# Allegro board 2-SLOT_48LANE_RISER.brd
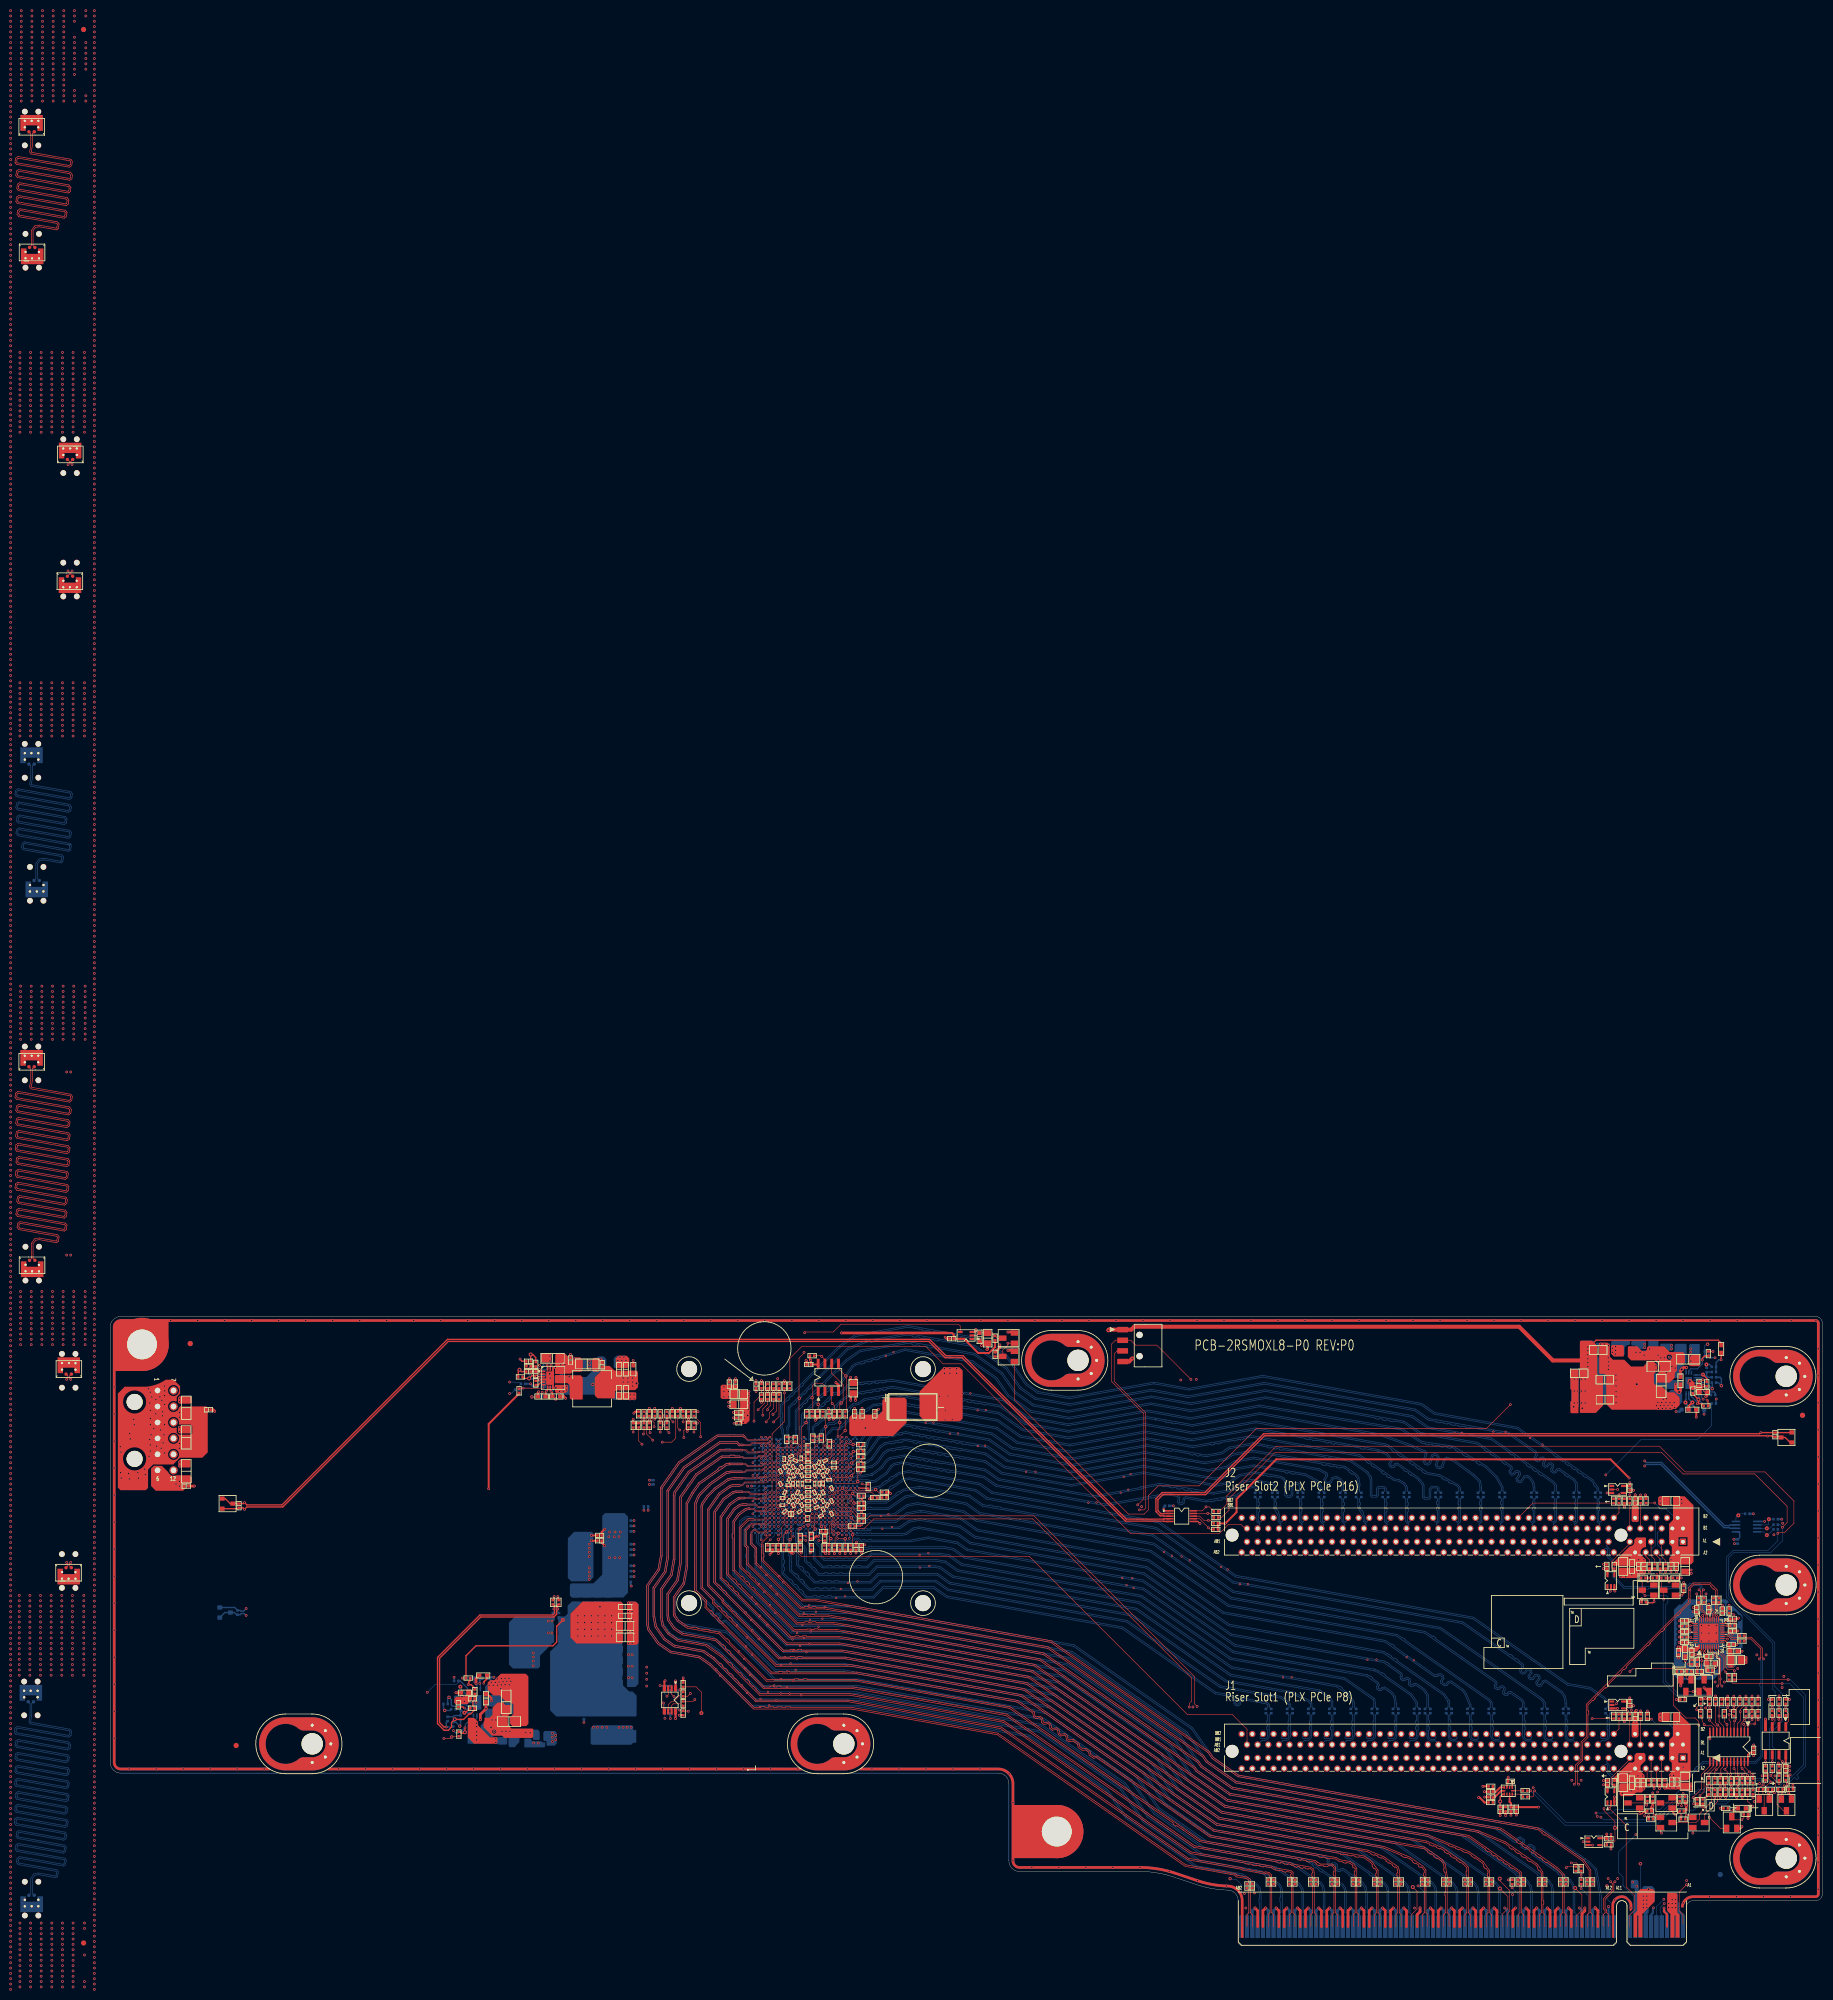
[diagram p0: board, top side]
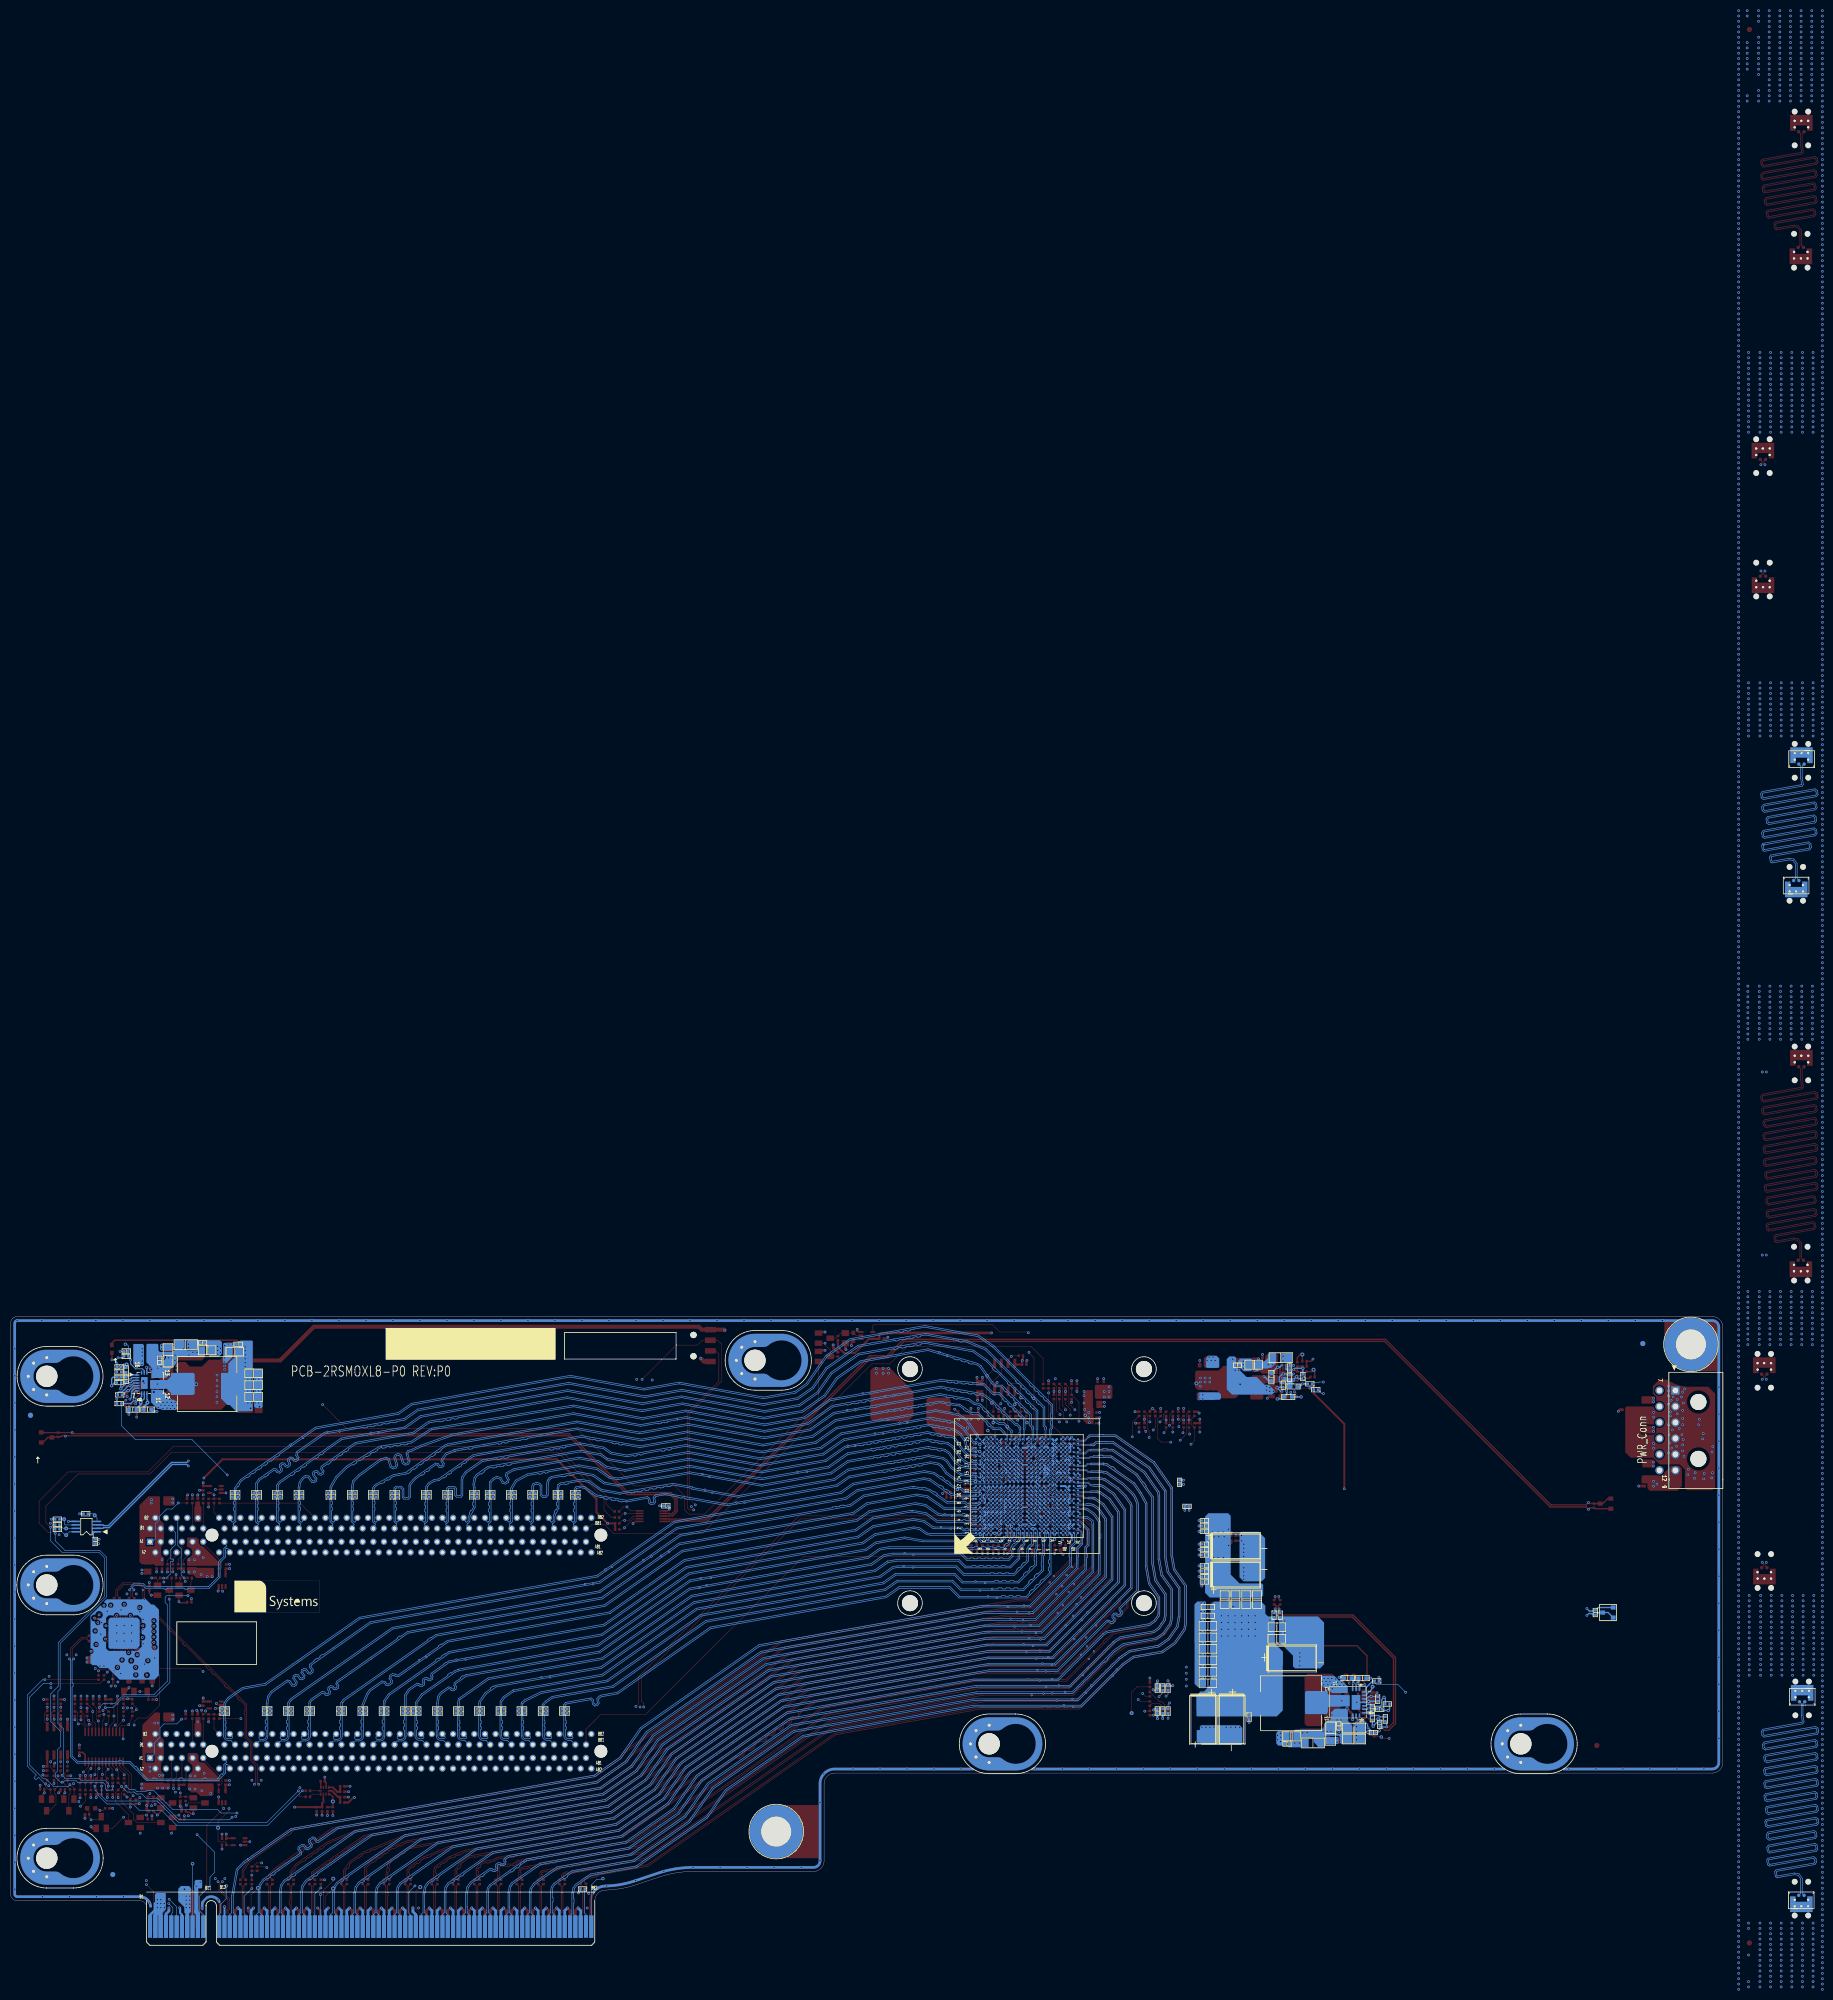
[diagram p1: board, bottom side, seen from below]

Outline 322.05 x 118.24 mm; copper layers: TOP, GND, IN1, VCC, VCC1, IN2, GND1, BOTTOM. Coordinates in mm from the lower left corner of the outline.
Outline path: 0,116.24 0,34.41 0.02,34.15 arc(0.07,33.89) 0.15,33.64 0.27,33.41 0.41,33.19 arc(0.59,32.99) 0.78,32.82 1,32.68 1.23,32.56 1.48,32.48 1.74,32.42 2,32.41 167.05,32.41 167.31,32.39 167.56,32.34 167.81,32.26 168.05,32.14 168.26,31.99 168.46,31.82 168.63,31.63 168.78,31.41 168.89,31.17 168.98,30.93 169.03,30.67 169.05,30.41 169.05,15.91 169.06,15.65 169.11,15.39 169.2,15.14 169.31,14.91 arc(169.46,14.69) 169.63,14.49 169.83,14.32 arc(170.05,14.18) 170.28,14.06 170.53,13.98 170.79,13.92 171.05,13.91 193.68,13.91 194.53,13.89 194.81,13.88 195.38,13.83 195.71,13.8 196.23,13.74 196.58,13.7 197.07,13.62 197.43,13.55 197.91,13.45 198.26,13.37 198.75,13.25 199.09,13.16 199.59,13.01 200,12.88 204.36,11.43 205.18,11.18 206,10.96 206.83,10.78 207.67,10.63 208.51,10.52 209.36,10.45 210.21,10.41 210.49,10.38 arc(210.9,10.27) 211.27,10.07 211.49,9.9 211.69,9.7 211.86,9.47 211.99,9.23 212.09,8.96 212.15,8.69 212.17,8.41 212.17,0.51 212.67,0 282.87,0 283.37,0.51 283.37,7.45 arc(284.33,8.41) 285.28,7.45 285.28,0.51 285.79,0 295.96,0 296.47,0.51 296.47,7.14 arc(296.84,8.04) 297.74,8.41 320.78,8.41 arc(321,8.43) 321.21,8.48 321.41,8.58 321.59,8.7 321.75,8.86 321.88,9.04 arc(321.97,9.24) 322.03,9.46 322.05,9.68 322.05,116.97 322.03,117.2 321.97,117.41 321.88,117.61 321.75,117.79 321.59,117.95 321.41,118.07 321.21,118.17 321,118.23 320.78,118.24 2,118.24 1.74,118.23 1.48,118.18 arc(1.12,118.04) 0.78,117.83 0.59,117.66 0.41,117.46 0.27,117.24 0.15,117.01 0.07,116.76 0.02,116.51 0,116.24

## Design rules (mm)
constraint set DEFAULT: min track width 0.102, pair gap 0.102

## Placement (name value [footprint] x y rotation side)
C1  -  [C0402]  131.4 109.22 180 top
C2  -  [C0201]  126.09 89.16 112.5 top
C3  -  [C0402]  135.21 99.95 90 top
C4  -  [C0201]  126.09 86.76 112.5 top
C5  -  [C0201]  128.09 91.96 22.5 top
C6  -  [C0201]  126.89 85.16 247.5 top
C7  -  [C0201]  127.69 89.16 67.5 top
C8  -  [C0402]  141.43 99.95 90 top
C9  -  [C0201]  128.49 89.96 292.5 top
C10  -  [C0201]  134.09 83.56 112.5 top
C11  -  [C0402]  97.51 73.41 0 bottom
C12  -  [C0402]  143.84 99.95 90 top
C13  -  [C0402]  97.51 74.42 0 bottom
C14  -  [C0201]  134.09 85.16 112.5 top
C15  -  [C0201]  127.69 83.56 67.5 top
C16  -  [C0201]  131.28 89.97 180 top
C17  -  [C0201]  126.89 89.96 112.5 top
C18  -  [C0201]  133.29 84.36 247.5 top
C19  -  [C0201]  134.89 82.76 247.5 top
C20  -  [C0201]  133.29 89.16 67.5 top
C21  -  [C0201]  135.69 83.56 292.5 top
C22  -  [C0201]  130.09 89.96 292.5 top
C23  -  [C0402]  278.83 11.94 270 top
C24  -  [C0402]  273.83 11.94 270 top
C25  -  [C0402]  269.83 11.94 270 top
C26  -  [C0402]  265.83 11.94 270 top
C27  -  [C0402]  281.26 44.07 270 bottom
C28  -  [C0402]  273.3 44.07 270 bottom
C29  -  [C0402]  269.3 44.07 270 bottom
C30  -  [C0402]  265.3 44.07 270 bottom
C31  -  [C0402]  282.28 44.07 270 bottom
C32  -  [C0402]  274.31 44.07 270 bottom
C33  -  [C0402]  270.31 44.07 270 bottom
C34  -  [C0402]  266.31 44.07 270 bottom
C35  -  [C0402]  277.82 11.94 270 top
C36  -  [C0402]  272.82 11.94 270 top
C37  -  [C0402]  268.82 11.94 270 top
C38  -  [C0402]  264.82 11.94 270 top
C39  -  [C0402]  280.34 84.71 270 bottom
C40  -  [C0402]  276.3 84.71 270 bottom
C41  -  [C0402]  272.37 84.71 270 bottom
C42  -  [C0402]  268.33 84.71 270 bottom
C43  -  [C0402]  279.33 84.71 270 bottom
C44  -  [C0402]  275.29 84.71 270 bottom
C45  -  [C0402]  271.35 84.71 270 bottom
C46  -  [C0402]  267.31 84.71 270 bottom
C47  -  [C0805]  118.24 101.73 180 top
C48  -  [C0805]  139.78 104.78 90 top
C49  -  [C0402]  118.24 100.2 180 top
C50  -  [C0402]  116.46 105.54 90 top
C51  -  [C0402]  118.24 99.19 180 top
C52  -  [C0402]  117.6 105.54 90 top
C53  -  [C0201#2]  131.17 80.24 270 top
C54  -  [C0201#2]  118.24 98.17 180 top
C55  -  [C0402]  259.3 44.07 270 bottom
C56  -  [C0402]  255.3 44.07 270 bottom
C57  -  [C0402]  251.3 44.07 270 bottom
C58  -  [C0402]  247.3 44.07 270 bottom
C59  -  [C0402]  245.26 44.07 270 bottom
C60  -  [C0402]  241.28 44.07 270 bottom
C61  -  [C0402]  237.31 44.07 270 bottom
C62  -  [C0402]  233.35 44.07 270 bottom
C63  -  [C0402]  229.31 44.07 270 bottom
C64  -  [C0402]  225.38 44.07 270 bottom
C65  -  [C0402]  221.38 44.07 270 bottom
C66  -  [C0402]  217.38 44.07 270 bottom
C67  -  [C0402]  260.31 44.07 270 bottom
C68  -  [C0402]  256.31 44.07 270 bottom
C69  -  [C0402]  252.31 44.07 270 bottom
C70  -  [C0402]  248.31 44.07 270 bottom
C71  -  [C0402]  246.28 44.07 270 bottom
C72  -  [C0402]  242.29 44.07 270 bottom
C73  -  [C0402]  238.33 44.07 270 bottom
C74  -  [C0402]  234.37 44.07 270 bottom
C75  -  [C0402]  230.33 44.07 270 bottom
C76  -  [C0402]  226.39 44.07 270 bottom
C77  -  [C0402]  222.39 44.07 270 bottom
C78  -  [C0402]  218.39 44.07 270 bottom
C79  -  [C0402]  259.83 11.94 270 top
C80  -  [C0402]  255.83 11.94 270 top
C81  -  [C0402]  251.83 11.94 270 top
C82  -  [C0402]  247.83 11.94 270 top
C83  -  [C0402]  242.83 11.94 270 top
C84  -  [C0402]  238.83 11.94 270 top
C85  -  [C0402]  234.83 11.94 270 top
C86  -  [C0402]  230.83 11.94 270 top
C87  -  [C0402]  226.83 11.94 270 top
C88  -  [C0402]  222.83 11.94 270 top
C89  -  [C0402]  218.83 11.94 270 top
C90  -  [C0402]  214.83 11.18 270 top
C91  -  [C0402]  258.82 11.94 270 top
C92  -  [C0402]  254.82 11.94 270 top
C93  -  [C0402]  250.82 11.94 270 top
C94  -  [C0402]  246.82 11.94 270 top
C95  -  [C0402]  241.82 11.94 270 top
C96  -  [C0402]  237.82 11.94 270 top
C97  -  [C0402]  233.82 11.94 270 top
C98  -  [C0402]  229.82 11.94 270 top
C99  -  [C0402]  225.82 11.94 270 top
C100  -  [C0402]  221.82 11.94 270 top
C101  -  [C0402]  217.82 11.94 270 top
C102  -  [C0402]  213.82 11.18 270 top
C103  -  [C0402]  262.33 84.71 270 bottom
C104  -  [C0402]  258.29 84.71 270 bottom
C105  -  [C0402]  254.33 84.71 270 bottom
C106  -  [C0402]  250.29 84.71 270 bottom
C107  -  [C0402]  244.36 84.71 270 bottom
C108  -  [C0402]  240.36 84.71 270 bottom
C109  -  [C0402]  235.34 84.71 270 bottom
C110  -  [C0402]  232.36 84.71 270 bottom
C111  -  [C0402]  228.36 84.71 270 bottom
C112  -  [C0402]  224.36 84.71 270 bottom
C113  -  [C0402]  219.6 84.71 270 bottom
C114  -  [C0402]  216.36 84.71 270 bottom
C115  -  [C0402]  261.32 84.71 270 bottom
C116  -  [C0402]  257.28 84.71 270 bottom
C117  -  [C0402]  253.32 84.71 270 bottom
C118  -  [C0402]  249.28 84.71 270 bottom
C119  -  [C0402]  243.34 84.71 270 bottom
C120  -  [C0402]  239.34 84.71 270 bottom
C121  -  [C0402]  234.33 84.71 270 bottom
C122  -  [C0402]  231.34 84.71 270 bottom
C123  -  [C0402]  227.34 84.71 270 bottom
C124  -  [C0402]  223.34 84.71 270 bottom
C125  -  [C0402]  218.58 84.71 270 bottom
C126  -  [C0402]  215.34 84.71 270 bottom
C127  -  [C0402]  121.49 105.16 270 top
C128  -  [C0201]  126.88 81.56 225 top
C129  -  [C0201]  127.56 86.54 0 top
C130  -  [C0201]  126.47 84.12 180 top
C131  -  [C0201]  130 91.57 270 top
C132  -  [C0201]  132.89 82.36 22.5 top
C133  -  [C0201]  134.09 81.96 292.5 top
C134  -  [C0201]  127.69 87.56 67.5 top
C135  -  [C0201]  127.81 81.13 270 top
C136  -  [C0201]  128.89 91.16 157.5 top
C137  -  [C0201]  134.49 91.16 22.5 top
C138  -  [C0201]  133.29 90.76 67.5 top
C139  -  [C0201]  127.69 90.76 247.5 top
C140  -  [C0201]  134.09 88.36 112.5 top
C141  -  [C0201]  135.69 85.96 292.5 top
C142  -  [C0201]  133.69 80.76 202.5 top
C143  -  [C0201]  135.23 87.56 0 top
C144  -  [C0201]  134.09 89.96 292.5 top
C145  -  [C0402]  140.29 74.8 270 top
C146  -  [C0201]  134.89 89.16 67.5 top
C147  -  [C0402]  141.3 74.8 270 top
C148  -  [C0201]  135.69 81.16 292.5 top
C149  -  [C0402]  97.51 71.37 0 bottom
C150  -  [C0201]  126.44 82.76 180 top
C151  -  [C0201]  136.15 90.79 0 top
C152  -  [C0402]  259.67 27.89 180 top
C153  -  [C0402]  259.67 28.91 180 top
C154  -  [C0603]  163.53 114.43 270 top
C155  -  [C0402]  158.27 114.07 180 top
C156  -  [C0805]  165.05 114.17 270 top
C160  -  [C0402]  140.03 99.95 90 top
C161  -  [C0201]  136.17 89.84 0 top
C162  -  [C0201]  126.78 91.46 270 top
C163  -  [C0201]  131.28 81.84 180 top
C164  -  [C0201]  129.69 81.56 208.4 top
C165  -  [TAJ_D_7-3X4-3]  97.74 42.42 270 bottom
C166  -  [TAJ_D_7-3X4-3]  91.54 69.72 180 bottom
C167  -  [TAJ_D_7-3X4-3]  91.54 75.06 180 bottom
C170  -  [TAJ_D_7-3X4-3]  92.41 42.42 270 bottom
C171  -  [TAJ_D_7-3X4-3]  150.95 101.22 0 top
C173  -  [TAJ_D_7-3X4-3]  80.98 53.98 180 bottom
C174  -  [C0402]  100.79 82.55 180 bottom
C175  -  [C0402]  92.05 77.09 180 top
C176  -  [C0402]  102.19 87.07 90 bottom
C177  -  [C0402]  92.05 76.07 180 top
C178  -  [C0402]  264.49 25.6 270 top
C179  -  [C0402]  263.48 25.6 270 top
C180  -  [C0402]  261.44 25.6 270 top
C181  -  [C0201]  134.09 86.84 90 top
C182  -  [C0402]  97.51 77.85 0 bottom
C183  -  [C0402]  97.51 79.88 0 bottom
C184  -  [C0402]  97.51 75.44 0 bottom
C185  -  [C0402]  97.51 68.33 0 bottom
C186  -  [C0402]  97.51 78.87 0 bottom
C187  -  [C0402]  97.51 69.34 0 bottom
C188  -  [C0402]  97.51 70.36 0 bottom
C194  -  [C0201]  128.32 81.13 270 top
C215  -  [C0603]  305.39 55.32 0 top
C216  -  [C0402]  296.12 59 180 top
C217  -  [C0402]  304.88 56.59 0 top
C218  -  [C0402]  300.68 63.12 90 top
C219  -  [C0402]  298.42 63.12 90 top
C220  -  [C0402]  296.12 56.97 180 top
C221  -  [C0402]  296.12 61.03 180 top
C222  -  [C0402]  303.22 62.87 90 top
C223  -  [C0402]  309.12 36.68 90 top
C224  -  [C0603]  296.25 55.07 270 top
C225  -  [C0402]  297.52 55.07 270 top
C226  -  [C0603]  301.07 53.03 0 top
C227  -  [C0402]  300.69 54.3 0 top
C242  -  [C0805]  296.24 71.25 270 top
C243  -  [C0402]  294.59 71.25 270 top
C244  -  [C0402]  293.57 71.25 270 top
C245  -  [C0603]  286.21 71.25 270 top
C246  -  [C0402]  288.49 71.25 270 top
C247  -  [C0402]  287.48 71.25 270 top
C248  -  [C0402]  286.84 83.57 90 top
C249  -  [C0805]  296.24 30.86 270 top
C250  -  [C0402]  293.7 30.73 270 top
C251  -  [C0402]  294.72 30.73 270 top
C252  -  [C0603]  286.21 30.61 270 top
C253  -  [C0402]  288.37 30.61 270 top
C254  -  [C0402]  287.35 30.61 270 top
C255  -  [C0402]  286.84 43.05 90 top
C257  -  [C0402]  305.14 61.39 0 top
C258  -  [C0402]  305.14 59.13 0 top
C259  -  [C0402]  306.15 75.95 270 bottom
C260  -  [C0402]  23.98 62.59 90 bottom
C265  -  [C0402]  198.81 82.65 0 bottom
C269  -  [C0201]  130.09 88.36 292.5 top
C271  -  [C0201]  130.09 84.36 292.5 top
C273  -  [C0201]  130.09 82.76 292.5 top
C275  -  [C0201]  132.49 88.36 292.5 top
C277  -  [C0201]  132.49 83.56 112.5 top
C279  -  [C0201]  129.29 85.16 67.5 top
C281  -  [C0201]  129.29 83.56 67.5 top
C283  -  [C0201]  131.28 88.24 180 top
C287  -  [C0201]  131.28 82.7 180 top
C290  -  [C0201]  131.28 83.56 0 top
C294  -  [C0201]  131.28 85.29 0 top
C297  -  [C0201]  131.28 84.43 180 top
C352  -  [C0402]  281.89 20.07 0 top
C386  -  [C0201]  128.49 82.76 292.5 top
C390  -  [C0201]  128.49 88.36 292.5 top
C394  -  [C0201]  131.28 86.16 180 top
C398  -  [C0201]  129.29 89.16 67.5 top
C402  -  [C0201]  131.28 87.37 0 top
C406  -  [C0201]  131.28 90.8 180 top
C410  -  [C0201]  131.28 89.1 0 top
C414  -  [C0201]  133.39 86.82 90 top
C418  -  [C0201]  132.49 85.16 112.5 top
C422  -  [C0201]  128.44 86.82 270 top
C426  -  [C0201]  129.32 86.82 90 top
C430  -  [C0201]  130.21 86.82 270 top
C434  -  [C0201]  132.5 86.82 270 top
C438  -  [C0201]  132.49 89.96 292.5 top
C442  -  [C0201]  128.49 84.36 292.5 top
C450  -  [C0402]  106.38 44.07 90 bottom
C451  -  [C0402]  106.38 48.39 270 bottom
C452  -  [C0402]  315.16 33.27 270 top
C455  -  [C0402]  281.51 71.25 90 top
C456  -  [C0402]  281.64 30.61 90 top
C460  -  [C0402]  285.83 85.98 270 top
C461  -  [C0402]  285.83 45.47 270 top
C463  -  [C1206]  14.3 101.09 90 top
C464  -  [C1206]  14.3 95.5 90 top
C465  -  [C0402]  18.49 100.71 0 top
C466  -  [C1206]  14.3 89.15 90 top
C467  -  [C0402]  14.3 86.36 0 top
C468  -  [C0402]  313.13 96.01 90 top
C469  -  [C0402]  24.23 82.68 270 top
C477  -  [C0805]  293.57 83.57 180 top
C478  -  [C0805]  284.56 71.25 270 top
C479  -  [C0805]  293.57 42.93 180 top
C480  -  [C0805]  284.56 30.61 270 top
CON1  -  [HEADER1X4S2NH_P2H2_RA]  193.63 112.78 270 top
D1  -  [LED0603]  306.91 25.78 0 top
H1  -  [HOLE_C10D5-6B10_NPB_H11_STANDOFF]  6 113 180 bottom
J1  -  [PCIE_X16D_H11]  295.83 35.25 270 top
J2  -  [PCIE_X16D_H11]  295.83 75.89 270 top
J5  -  [GF_PCIE_X16]  284.33 7.45 180 bottom
J6  -  [PWR2X6D2NH_P3W3H8-9_RA]  8.92 104.32 90 bottom
L1  -  [B2012]  305.77 53.67 0 top
L2  -  [B2012]  118.24 103.63 180 top
L3  -  [B2012]  87.61 65.02 90 bottom
L4  -  [B2012]  89.64 65.02 90 bottom
L5  -  [B2012]  93.7 65.02 90 bottom
L6  -  [B2012]  91.67 65.02 90 bottom
ME1  -  [LABEL20X4_SST21X5]  217.88 110.24 180 bottom
ME2  -  [LABEL_32X6_FULL]  251.54 110.11 180 bottom
ME3  -  [ZT_LOG_6X16]  279.99 62.61 180 bottom
MH1  -  [HOLE_D3N_PKO10]  108.89 64.36 0 top
MH2  -  [HOLE_D3N_PKO10]  152.89 64.36 0 top
MH3  -  [HOLE_D3N_PKO10]  152.89 108.36 0 top
MH4  -  [HOLE_D3N_PKO10]  108.89 108.36 0 top
MH5  -  [GND_C10D4_6-5B10_OB5]  138 37.9 270 top
MH6  -  [GND_C10D4_6-5B10_OB5]  315.25 16.41 270 top
MH7  -  [GND_C10D4_6-5B10_OB5]  315.25 67.77 270 top
MH8  -  [HOLE_C10D5-6B10_NPB_H11_STANDOFF]  178.05 21.41 180 bottom
MH9  -  [GND_C10D4_6-5B10_OB5]  182.05 110 270 top
MH10  -  [GND_C10D4_6-5B10_OB5]  38 37.9 270 top
MH11  -  [GND_C10D4_6-5B10_OB5]  315.25 107 270 top
NOREF  -  [unnamed]  15.06 113.16 0 top
NOREF#2  -  [#2]  302.74 48.77 180 top
NOREF#3  -  [unnamed]  23.7 37.59 0 top
NOREF#4  -  [unnamed]  318.31 99.67 0 top
NOREF#5  -  [#2]  310.59 53.87 180 top
NOREF#6  -  [#2]  299.29 66.86 0 top
NOREF#7  -  [unnamed]  -5 0.47 0 top
NOREF#8  -  [#2]  275.79 30.3 180 top
NOREF#9  -  [#2]  18.67 -76.43 0 top
NOREF#10  -  [unnamed]  -5 360.19 0 top
NOREF#11  -  [unnamed]  302.85 13.34 180 bottom
NOREF#12  -  [unnamed]  15.06 113.16 180 bottom
NOREF#13  -  [unnamed]  290.78 52.83 180 bottom
NOREF#14  -  [unnamed]  318.31 99.67 180 bottom
PC506  -  [C0402]  300.31 111.74 0 bottom
PC508  -  [C0603]  296.3 100.75 0 bottom
PC509  -  [C0402]  298.84 105.65 270 top
PC510  -  [C0603]  299.07 100.75 0 bottom
PC511  -  [C0402]  293.99 109.99 90 bottom
PC514  -  [C0603]  295.36 106.18 270 top
PC515  -  [C1206]  292.44 110.93 90 bottom
PC516  -  [C0402]  300.3 106.43 90 bottom
PC517  -  [C1206]  291.73 105.19 270 top
PC518  -  [C0402]  301.66 106.82 180 bottom
PC519  -  [C1206]  296.83 110.22 0 top
PC520  -  [C1206]  291.24 108.87 180 top
PC521  -  [C1206]  289.11 112.94 180 bottom
PC522  -  [C0402]  279.26 113.03 0 bottom
PC524  -  [C0805]  276.33 107.55 180 top
PC526  -  [C0805]  276.34 105.34 180 bottom
PC527  -  [C0402]  301.65 108.77 0 bottom
PC529  -  [C0805]  276.34 107.55 180 bottom
PC530  -  [C0805]  281.16 102.62 0 top
PC531  -  [C0805]  276.34 103.11 180 bottom
PC532  -  [C0402]  285.95 113.29 0 bottom
PC533  -  [C0805]  279.89 111.63 0 bottom
PC539  -  [C0402]  81.48 108.56 90 bottom
PC541  -  [C0603]  83.92 103.21 0 top
PC542  -  [C0603]  81.15 103.21 180 top
PC543  -  [C0402]  86.59 110.06 90 top
PC545  -  [C1206]  89.74 109.33 0 top
PC546  -  [C0603]  84.91 106.84 270 bottom
PC547  -  [C0402]  80.04 107.49 90 top
PC548  -  [C1206]  83.2 110.37 180 top
PC549  -  [C0402]  78.68 107.88 0 top
PC550  -  [C1206]  83.16 110.49 180 bottom
PC551  -  [C0402]  92.53 109.17 90 top
PC552  -  [C0603]  97 108.33 90 top
PC553  -  [C0402]  91.29 109.09 0 bottom
PC554  -  [C0603]  97 104.01 270 top
PC555  -  [C0402]  78.69 109.84 180 top
PC556  -  [C0603]  95.73 104.01 270 top
PC557  -  [C0603]  95.73 108.33 90 top
PC580  -  [C0402]  65.74 40.02 180 bottom
PC581  -  [C0603]  70.55 50.26 180 bottom
PC582  -  [C0402]  65.48 45.24 90 top
PC583  -  [C0603]  67.78 50.26 180 bottom
PC584  -  [C0402]  72.23 41.27 270 bottom
PC585  -  [C1206]  69.38 38.8 180 bottom
PC586  -  [C1206]  77.11 38.07 0 bottom
PC587  -  [C0603]  70.69 46.51 90 top
PC588  -  [C1206]  74.49 45.81 90 top
PC589  -  [C0402]  65.92 44.58 270 bottom
PC591  -  [C0402]  64.54 44.41 0 bottom
PC592  -  [C0402]  89.1 42.95 270 bottom
PC593  -  [C0402]  81.98 37.89 180 bottom
PC594  -  [C0805]  83.9 57.66 180 bottom
PC595  -  [C0805]  96.85 55.75 0 bottom
PC596  -  [C0805]  96.85 57.91 0 top
PC597  -  [C0402]  64.53 41.57 270 bottom
PC598  -  [C0805]  96.85 49.28 0 bottom
PC599  -  [C0805]  96.85 51.44 0 bottom
PC600  -  [C0805]  96.85 60.07 0 top
PC788  -  [C1206]  75.01 42.06 0 top
PC1531  -  [C0805]  279.87 111.95 0 top
PC1533  -  [C0805]  281.12 106.38 0 top
PC1588  -  [C1206]  73.78 39.82 270 bottom
PC1589  -  [C1206]  69.38 40.87 180 bottom
PC1592  -  [C0603]  96.85 63.63 0 top
PC1594  -  [C0603]  96.85 61.98 0 bottom
PC1595  -  [C0603]  96.85 61.98 0 top
PC1596  -  [C0805]  83.87 59.82 180 bottom
PC1598  -  [C0805]  96.85 57.91 0 bottom
PC1599  -  [C0805]  96.85 60.07 0 bottom
PC1600  -  [C0805]  96.85 53.59 0 bottom
PC2596  -  [C0603]  96.85 63.63 0 bottom
PL6  -  [IND_PCMB104TXA]  285.1 105.54 180 bottom
PL8  -  [IND_PCMC063T]  90.65 104.65 0 top
PL9  -  [B2012]  88.24 109.19 0 bottom
PL11  -  [IND_PCMB104T]  81.21 45.53 0 bottom
PL12  -  [B2012]  285.08 111.9 180 bottom
PL20  -  [B2012]  81.13 39.31 0 bottom
PR332  -  [R0402]  300.62 111.27 270 top
PR333  -  [R0402]  300.3 110.75 0 bottom
PR336  -  [R0402]  301.63 101.88 180 bottom
PR339  -  [R0402]  301.51 103.5 0 bottom
PR340  -  [R0603]  299.6 104.02 0 top
PR341  -  [R0603]  297.59 100.72 180 top
PR342  -  [R0402]  301.65 105.83 0 bottom
PR343  -  [R0402]  297.69 104.23 270 top
PR344  -  [R0402]  300.31 105.57 90 top
PR345  -  [R0402]  300.13 101.42 0 top
PR346  -  [R0402]  300.3 108.18 90 bottom
PR347  -  [R0402]  301.65 107.81 0 bottom
PR348  -  [R0603]  303 112.14 90 top
PR357  -  [R0402]  76.56 104.47 0 bottom
PR361  -  [R0402]  77.67 105.59 0 bottom
PR363  -  [R0402]  76.91 104.27 90 top
PR366  -  [R0402]  82.67 105.33 90 bottom
PR367  -  [R0402]  81.51 106.82 270 bottom
PR368  -  [R0402]  80.06 105.77 90 top
PR369  -  [R0603]  80.74 105.09 180 bottom
PR370  -  [R0603]  81.74 103.12 0 bottom
PR371  -  [R0402]  77.17 106.88 180 top
PR372  -  [R0402]  79 106.96 90 bottom
PR373  -  [R0402]  80.04 109.25 90 top
PR374  -  [R0402]  78.69 108.87 180 top
PR375  -  [R0603]  98.4 108.33 270 top
PR418  -  [R0402]  65.6 39.74 90 top
PR420  -  [R0402]  65.09 49.74 0 bottom
PR423  -  [R0402]  64.94 46.31 270 bottom
PR424  -  [R0603]  66.72 47.51 180 top
PR426  -  [R0603]  70.16 50.75 180 top
PR427  -  [R0402]  63.09 45.4 180 bottom
PR428  -  [R0402]  68.6 47.72 90 top
PR429  -  [R0402]  68.15 44.6 180 top
PR430  -  [R0402]  67.34 50.27 180 top
PR431  -  [R0402]  65.92 42.82 270 bottom
PR432  -  [R0402]  63.47 42.59 270 bottom
PR433  -  [R0402]  84.41 62.1 270 bottom
PR434  -  [R0402]  84.41 64.52 90 top
PR435  -  [R0402]  83.26 64.52 90 top
PR504  -  [R0402]  68.15 46.38 0 top
PR505  -  [R0402]  83.26 62.1 270 bottom
PU17  -  [PQFN17_IR3899]  295.77 105.75 270 bottom
PU19  -  [PQFN16_IR3823]  83.31 106.66 270 top
PU23  -  [PQFN17_IR3895]  70.65 45.71 90 bottom
Q1  -  [SOT23_GDS]  168.99 110.74 180 top
Q2  -  [SOT23_GDS]  168.99 114.17 180 top
Q3  -  [SOT23_GDS]  296.37 48.84 270 top
Q4  -  [SOT23_GDS]  299.8 48.84 90 top
Q5  -  [SOT23]  315.29 95.5 180 top
Q6  -  [SOT23]  22.07 83.06 0 top
Q7  -  [SOT23_GDS]  305 23.11 90 top
Q15  -  [SOT23_GDS]  293.32 66.8 180 top
Q18  -  [SOT23_GDS]  289.26 66.8 180 top
Q19  -  [SOT23_GDS]  315.29 26.42 270 top
Q20  -  [SOT23_GDS]  298.78 23.11 0 top
Q21  -  [SOT23_GDS]  292.69 26.8 180 top
Q22  -  [SOT23_GDS]  311.1 26.42 270 top
Q23  -  [SOT23_GDS]  292.69 23.11 0 top
Q24  -  [SOT23_GDS]  286.59 26.8 180 top
Q25  -  [SOT23]  21.62 62.59 0 bottom
R1  -  [R0402]  297.52 53.29 90 top
R2  -  [R0402]  298.53 53.29 270 top
R3  -  [R0402]  295.73 46.23 0 top
R4  -  [R0402]  298.91 51.51 0 top
R5  -  [R0402]  285.83 43.05 270 top
R6  -  [R0402]  285.83 83.57 270 top
R7  -  [R0402]  305.13 60.07 180 top
R8  -  [R0402]  296.12 60.02 0 top
R9  -  [R0402]  276.68 11.94 90 top
R10  -  [R0402]  139.63 78.87 0 top
R11  -  [R0402]  107.77 99.95 90 top
R12  -  [R0402]  104.73 99.95 270 top
R13  -  [R0402]  123.65 105.16 270 top
R14  -  [R0402]  124.79 105.16 270 top
R15  -  [R0402]  129.82 76.64 90 top
R16  -  [R0402]  141.3 79.78 0 top
R17  -  [R0402]  141.3 80.77 0 top
R18  -  [R0402]  141.3 84.52 0 top
R19  -  [R0402]  128.86 95.12 90 top
R20  -  [R0402]  133.76 95.39 90 top
R21  -  [R0402]  305.39 43.56 90 top
R22  -  [R0402]  303.61 43.56 90 top
R23  -  [R0402]  141.18 90.49 0 top
R24  -  [R0402]  141.18 89.47 0 top
R25  -  [R0402]  300.81 43.56 90 top
R26  -  [R0402]  299.16 43.56 90 top
R27  -  [R0402]  300.69 30.99 270 top
R28  -  [R0402]  301.83 30.99 270 top
R29  -  [R0402]  302.85 30.99 270 top
R30  -  [R0402]  303.86 30.99 270 top
R31  -  [R0402]  104.73 97.79 90 top
R32  -  [R0402]  103.46 99.95 270 top
R33  -  [R0402]  109.81 97.79 90 top
R34  -  [R0402]  123.65 103.12 90 top
R35  -  [R0402]  102.44 99.95 90 top
R36  -  [R0402]  131.91 76.9 270 top
R37  -  [R0402]  141.3 82.17 0 top
R38  -  [R0402]  141.3 83.12 0 top
R39  -  [R0402]  127.26 95.17 90 top
R40  -  [R0402]  141.18 94.17 0 top
R41  -  [R0402]  141.18 91.88 0 top
R42  -  [R0402]  142.57 86.28 270 top
R43  -  [R0402]  106.76 99.95 90 top
R44  -  [R0402]  128.73 74.8 270 top
R45  -  [R0402]  127.84 105.16 90 top
R46  -  [R0402]  139.27 74.8 90 top
R47  -  [R0402]  129.82 74.8 90 top
R48  -  [R0402]  126.82 105.16 270 top
R49  -  [R0402]  108.79 97.79 270 top
R50  -  [R0402]  127.71 74.8 90 top
R51  -  [R0402]  105.74 99.95 270 top
R52  -  [R0402]  101.42 97.79 270 top
R53  -  [R0402]  131.9 74.8 90 top
R54  -  [R0402]  126.7 74.8 90 top
R55  -  [R0402]  100.41 99.95 90 top
R56  -  [R0402]  100.41 97.79 270 top
R57  -  [R0402]  131.27 91.95 90 top
R58  -  [R0402]  131.27 93.6 90 top
R59  -  [R0402]  103.46 97.79 90 top
R60  -  [R0402]  145.62 85.22 180 top
R61  -  [R0402]  134.19 77.79 0 top
R62  -  [R0402]  145.62 84.2 180 top
R63  -  [R0402]  143.84 84.2 180 top
R64  -  [R0402]  109.81 99.95 270 top
R65  -  [R0402]  141.18 92.9 0 top
R66  -  [R0402]  132.16 95.38 90 top
R67  -  [R0402]  124.79 103.12 90 top
R68  -  [R0402]  135.26 94.3 90 top
R69  -  [R0402]  108.79 99.95 90 top
R70  -  [R0402]  125.81 103.12 270 top
R71  -  [R0402]  98.38 97.79 90 top
R72  -  [R0402]  124.66 74.8 90 top
R73  -  [R0402]  125.68 74.8 270 top
R74  -  [R0402]  123.65 74.8 90 top
R75  -  [R0402]  134.39 76.52 90 top
R76  -  [R0402]  304.5 62.87 270 top
R77  -  [R0402]  296.12 57.99 0 top
R78  -  [R0402]  307.67 43.56 270 top
R79  -  [R0402]  306.96 28.8 90 top
R80  -  [R0402]  306.96 30.96 90 top
R81  -  [R0402]  308.81 45.85 270 top
R82  -  [R0402]  308.81 43.56 270 top
R83  -  [R0402]  309.96 45.85 270 top
R84  -  [R0402]  309.96 43.56 270 top
R85  -  [R0402]  308.99 28.8 90 top
R86  -  [R0402]  307.98 28.8 90 top
R87  -  [R0402]  307.98 30.96 270 top
R88  -  [R0402]  308.99 30.96 270 top
R89  -  [R0402]  304.5 50.37 90 top
R90  -  [R0402]  305.52 50.37 90 top
R91  -  [R0402]  300.94 51.76 180 top
R92  -  [R0402]  294.98 55.07 90 top
R93  -  [R0402]  138.25 74.8 90 top
R94  -  [R0402]  134.29 74.8 90 top
R95  -  [R0402]  307.67 45.85 270 top
R96  -  [R0402]  306.53 45.85 270 top
R97  -  [R0402]  305.39 45.85 270 top
R98  -  [R0402]  304.24 45.85 270 top
R99  -  [R0402]  303.1 45.85 270 top
R100  -  [R0402]  301.96 45.85 270 top
R101  -  [R0402]  300.81 45.85 270 top
R102  -  [R0402]  299.16 45.85 270 top
R103  -  [R0402]  300.69 28.83 90 top
R104  -  [R0402]  301.83 28.83 90 top
R105  -  [R0402]  302.85 28.83 90 top
R106  -  [R0402]  303.86 28.83 90 top
R107  -  [R0402]  295.96 67.16 270 top
R108  -  [R0402]  135.21 74.8 270 top
R109  -  [R0402]  307.67 24.64 180 top
R110  -  [R0402]  303.86 25.78 180 top
R111  -  [R0402]  137.24 74.8 90 top
R112  -  [R0402]  136.22 74.8 270 top
R113  -  [R0402]  99.39 99.95 270 top
R114  -  [R0402]  99.39 97.79 90 top
R115  -  [R0402]  122.51 105.16 270 top
R116  -  [R0402]  122.51 103.12 270 top
R117  -  [R0402]  125.81 105.16 90 top
R118  -  [R0402]  134.06 99.95 90 top
R119  -  [R0402]  131.01 99.95 90 top
R120  -  [R0402]  136.22 99.95 90 top
R121  -  [R0402]  132.03 99.95 90 top
R122  -  [R0402]  299.79 64.9 90 top
R123  -  [R0402]  298.78 64.9 90 top
R124  -  [R0402]  306.91 57.22 0 top
R125  -  [R0402]  306.91 58.24 0 top
R126  -  [R0402]  302.59 64.9 90 top
R127  -  [R0402]  301.57 64.9 90 top
R128  -  [R0402]  133.05 99.95 90 top
R129  -  [R0402]  132.03 110.87 0 top
R130  -  [R0402]  137.24 99.95 270 top
R131  -  [R0402]  138.25 99.95 270 top
R132  -  [R0402]  275.67 14.43 270 top
R133  -  [R0402]  276.68 14.43 270 top
R134  -  [R0402]  214.48 10.62 0 bottom
R135  -  [R0402]  263.35 30.86 180 top
R137  -  [R0402]  207.95 78.21 180 top
R141  -  [R0402]  207.95 79.35 180 top
R142  -  [R0402]  284.81 43.05 90 top
R143  -  [R0402]  284.81 83.57 90 top
R144  -  [R0402]  298.53 27.05 90 top
R145  -  [R0402]  299.54 27.05 90 top
R146  -  [R0402]  259.67 26.87 0 top
R147  -  [R0402]  262.46 25.6 90 top
R148  -  [R0402]  259.67 29.92 0 top
R150  -  [R0402]  304.93 30.96 270 top
R151  -  [R0402]  305.94 30.96 270 top
R152  -  [R0402]  263.7 11.94 270 top
R153  -  [R0402]  288.44 64.54 0 top
R154  -  [R0402]  281.89 18.92 0 top
R156  -  [R0402]  294.34 69.09 180 top
R157  -  [R0402]  266.14 29.08 0 top
R158  -  [R0402]  266.14 27.94 0 top
R159  -  [R0402]  290.53 69.09 180 top
R160  -  [R0402]  316.1 29.36 180 top
R161  -  [R0402]  295.86 23.75 0 top
R162  -  [R0402]  295.61 25.27 180 top
R163  -  [R0402]  312.24 29.34 180 top
R183  -  [R0402]  208 81.6 180 top
R184  -  [R0402]  208 80.46 180 top
R185  -  [R0402]  304.93 28.8 90 top
R186  -  [R0402]  305.94 28.8 90 top
R191  -  [R0402]  289.76 23.75 0 top
R192  -  [R0402]  289.51 25.27 180 top
R193  -  [R0402]  315.16 31.5 270 top
R194  -  [R0402]  107.77 43.69 90 top
R199  -  [R0402]  288.88 83.57 90 top
R200  -  [R0402]  289.13 43.05 90 top
R203  -  [R0402]  296.24 27.56 90 top
R204  -  [R0402]  311.35 31.5 270 top
R209  -  [R0402]  107.77 49.02 270 top
R210  -  [R0402]  290.15 27.56 90 top
R211  -  [R0402]  104.34 44.07 270 bottom
R214  -  [R0402]  283.8 83.57 270 top
R215  -  [R0402]  282.78 83.57 270 top
R216  -  [R0402]  283.8 43.05 270 top
R221  -  [R0402]  282.78 43.05 270 top
R226  -  [R0402]  292.18 69.09 0 top
R227  -  [R0402]  288.37 69.09 0 top
R228  -  [R0402]  295.23 27.56 90 top
R233  -  [R0402]  289.13 27.56 90 top
R234  -  [R0402]  107.77 45.47 270 top
R235  -  [R0402]  107.77 47.24 90 top
R236  -  [R0402]  314.15 29.34 0 top
R237  -  [R0402]  310.47 29.34 180 top
R252  -  [R0402]  287.86 83.57 270 top
R257  -  [R0402]  291.54 71.25 90 top
R258  -  [R0402]  290.53 71.25 90 top
R259  -  [R0402]  289.51 71.25 90 top
R260  -  [R0402]  292.56 71.25 90 top
R261  -  [R0402]  287.86 43.05 270 top
R262  -  [R0402]  291.42 30.61 90 top
R263  -  [R0402]  290.4 30.61 90 top
R264  -  [R0402]  289.38 30.61 90 top
R275  -  [R0402]  292.43 30.61 90 top
R277  -  [R0402]  105.36 48.39 270 bottom
R278  -  [R0402]  104.34 48.39 270 bottom
R279  -  [R0402]  311.35 33.27 270 top
R280  -  [R0402]  312.62 33.27 270 top
R281  -  [R0402]  315.16 45.85 270 top
R282  -  [R0402]  315.16 43.69 270 top
R283  -  [R0402]  313.89 45.85 270 top
R284  -  [R0402]  313.89 43.69 270 top
R285  -  [R0402]  312.62 45.85 270 top
R286  -  [R0402]  312.62 43.69 270 top
R293  -  [R0402]  313.89 31.5 90 top
R294  -  [R0402]  313.89 33.27 90 top
R296  -  [R0402]  105.36 44.07 90 bottom
R297  -  [R0402]  295.1 51.51 0 top
R298  -  [R0402]  297.01 51.51 180 top
R299  -  [R0402]  313.26 78.23 180 bottom
R300  -  [R0402]  313.26 79.12 180 bottom
R301  -  [R0402]  313.26 80.14 180 bottom
R302  -  [R0402]  307.93 81.15 180 bottom
R318  -  [R0402]  101.42 99.95 90 top
R348  -  [R0402]  166.45 111.12 270 top
R351  -  [R0402]  166.45 114.17 90 top
R352  -  [R0402]  282.91 71.25 270 top
R353  -  [R0402]  282.91 30.61 270 top
U1  -  [BGA575_0-8_19-1X21]  130.89 86.36 90 bottom
U2  -  [TSSOP24_P0-65W5-6H1-2]  304.47 37.34 270 top
U3  -  [X2QFN10_0-5_2X1-5]  262.97 29.08 270 top
U4  -  [MSOP8_P0-65H1-1]  307.8 78.74 0 bottom
U5  -  [DELTAL_COUPON_7P]  -14.65 317.93 0 top
U6  -  [SOIC8]  135.08 106.81 90 top
U7  -  [SOIC8]  313.26 38.48 270 top
U8  -  [SC70-5XB]  279.06 19.51 0 top
U9  -  [VFQFPN40_P0-4_EPAD]  300.71 58.7 90 top
U10  -  [MSOP10_P0-5W4-4_3X3]  201.53 80.71 0 top
U11  -  [SC70-5XB]  160.99 114.68 180 top
U12  -  [TSSOP8_D65_1D2]  105.29 46.16 270 top
U16  -  [SC70-5XB]  282.27 68.58 90 top
U17  -  [SC70-5XB]  282.27 27.94 90 top
U19  -  [SC70-5XB]  283.54 85.72 0 top
U20  -  [SC70-5XB]  283.54 45.21 0 top
U25  -  [DELTAL_COUPON_7P]  -7.54 280.67 180 top
U26  -  [DELTAL_COUPON_7P]  -14.78 342.26 180 top
U29  -  [DELTAL_COUPON_7P]  -7.54 256.11 0 top
U30  -  [DELTAL_COUPON_7P]  -14.65 127.51 0 top
U33  -  [DELTAL_COUPON_7P]  -7.8 69.72 0 top
U34  -  [DELTAL_COUPON_7P]  -14.78 166.5 180 top
U37  -  [DELTAL_COUPON_7P]  -7.8 108.71 180 top
U39  -  [DELTAL_COUPON_7P]  -14.78 223.39 0 bottom
U41  -  [DELTAL_COUPON_7P]  -13.82 198.91 180 bottom
U43  -  [DELTAL_COUPON_7P]  -14.78 8.13 180 bottom
U45  -  [DELTAL_COUPON_7P]  -14.91 47.12 0 bottom

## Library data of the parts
C1 C8 C11 C13 C145 C147 C149 C155 C182 C184 C186 C216-C223 C225 C227 C243 C244 C246-C248 C250 C251 C253-C255 C257-C259 C265 C352 C450-C452 C455 C456 C460 C461 C465 PC522 PC532 PC551 PC553 PC592 PC593 = CAP: part number: CAP_0402-0.1UF,CAP-42E000D1-D0,X7R,10%,16V
C2 C4 C6 C9 C15 C19 C133-C141 C143 C151 C161 C163 C386 C390 C394 C398 C402 C406 C410 C414 C418 C422 C426 C430 C434 C438 C442 = CAP: alternate symbols: C0201_BGA; part number: CAP_-0.1UF,CAP-21D000D1-D0,X7R,10%,10V
C3 C12 C127 C160 C183 C185 C187 C188 PC518 = CAP: part number: CAP_0402-0.01UF,CAP-42E00D01-D0,X7R,10%,16V
C5 C7 C10 C14 C16-C18 C20-C22 C53 C54 C128-C132 C142 C144 C146 C148 C150 C162 C164 C181 C194 C269 C271 C273 C275 C277 C279 C281 C283 C287 C290 C294 C297 = CAP: alternate symbols: C0201_BGA; part number: CAP_-0.01UF,CAP-21E00D01-D0,X7R,10%,16V
C23-C46 C55-C126 = CAP: part number: CAP_0402-0.22UF,CAP-42E00D22-D0,X7R,10%,16V
C47 C48 C477-C480 = CAP: part number: CAP_0805-22UF,CAP-85E00022-E0,X6S,20%,16V
C49-C52 C174-C177 = CAP: part number: CAP_0402-4.7UF,CAP-42C004D7-E0,X6S,20%,6.3V
C152 C153 C180 = CAP: part number: CAP_0402-0.47UF,CAP-42D00D47-D0,X7R,10%,10V
C154 = CAP: part number: CAP_-22UF,CAP-63C00022-E0,X6S,20%,6.3V
C156 = CAP: part number: CAP_0805-22UF,CAP-85C00022-E0,EMPTY,20%,6.3V
C165-C167 C171 = CAPP: part number: CAPP_-680UF,CAP-PLJ00680-E0,POLCAP,20%,2.5V
C170 C173 = CAPP: part number: CAPP_-680UF,CAP-PLJ00680-E0,EMPTY,20%,2.5V
C178 PC511 PC543 PC584 = CAP: part number: CAP_0402-0.1UF,CAP-42F000D1-D0,X7R,10%,25V
C179 = CAP: part number: CAP_0402-1UF,CAP-42D00001-D1,X7R,10%,10V
C215 C224 C226 C245 C252 = CAP: part number: CAP_0603-10UF,CAP-63C00010-E0,X7T,20%,6.3V
C242 C249 = CAP: part number: CAP_0805-10UF,CAP-85E00010-D0,X6S,10%,16V
C260 C468 C469 PC527 PC555 PC597 = CAP: part number: CAP_0402-2200PF,CAP-42GD0022-D0,X7R,10%,50V
C463 C464 PC515 PC517 PC519-PC521 PC545 PC548 PC585 PC586 PC588 PC788 PC1588 PC1589 = CAP: part number: CAP_1206-22UF,CAP-C6F00022-E0,X6S,20%,25V
C466 PC550 = CAP: part number: CAP_1206-22UF,CAP-C6F00022-E0,EMPTY,20%,25V
C467 = CAP: part number: CAP_0402-0.1UF,CAP-42E000D1-D0,EMPTY,10%,16V
CON1 = HEADER1X4: part number: HEADER1X4_-HEADER1X4S_P2_RA,COH-004SM200-00,IO,,
D1 = LED_2P: part number: LED_2P_-LTST-C193KGKT-5A,LED-S1SG000V-00,IC,,
H1 MH8 = STANDOFF: part number: STANDOFF_-HOLE_C10D5-6B10_NPB_H11_STANDOFF,TSW-AM3L5P1P-00,EMPTY,,
J1 J2 = PCIE_X16: part number: PCIE_X16_-2EG08213-9ADM-JF,COB-PCE164DV-03,IO,,
J5 = GF_PCIE_X16: part number: GF_PCIE_X16_-GF_PCIE_X16,,,,
J6 = PWR2X6: part number: PWR2X6_-2NH_PWR2X6,COP-012D0003-02,IO,,,
L1 = BEAD: part number: BEAD_-600,BED-06002012-00,IC,25%,,
L2 = BEAD: part number: BEAD_-330,BED-03302013-00,IC,25%,,
L3-L6 PL9 PL12 PL20 = BEAD: part number: BEAD_-22,BED-00222012-00,IC,25%,,
ME1 = DUMMY_SYMBOL_NO_PIN: part number: DUMMY_SYMBOL_NO_PIN_-LABEL20X4_SST21X5,MEDUMMY5,EMPTY,,
ME2 = DUMMY_SYMBOL_NO_PIN: part number: DUMMY_SYMBOL_NO_PIN_-LABEL_32X6_FULL,MEDUMMY7,EMPTY,,
ME3 = DUMMY_SYMBOL_NO_PIN: part number: DUMMY_SYMBOL_NO_PIN_-ZT_LOG_6X16,MEDUMMY3,EMPTY,,
MH1-MH4 = GRD_HOLE: part number: GRD_HOLE_-HOLE_D3N_PKO10,GRD_HOLE4,EMPTY
MH5-MH7 MH9-MH11 = SCREW_NP_5VIA: part number: SCREW_NP_5VIA_-C10D4XC10D6.5_5V,TEMP_C10D4XC10D6.5_L5,EMPTY,,
PC506 = CAP: part number: CAP_0402-0.01UF,CAP-42G00D01-D0,X7R,10%,50V
PC508 PC541 PC581 = CAP: part number: CAP_0603-2.2UF,CAP-63D002D2-D0,X7R,10%,10V
PC509 PC582 = CAP: part number: CAP_0402-100PF,CAP-42GD0001-C0,NP0,5%,50V
PC510 PC542 PC583 = CAP: part number: CAP_0603-1UF,CAP-63F00001-D0,X7R,10%,25V
PC514 PC546 PC587 = CAP_0603-0.1UF,CAP-63G000D1-D0A
PC516 PC589 = CAP: part number: CAP_0402-150PF,CAP-42G0150P-C0,NP0,5%,50V
PC524 PC526 PC529-PC531 PC533 PC1531 PC1533 = CAP: part number: CAP_0805-22UF,CAP-85C00022-E0,X6S,20%,6.3V
PC539 PC580 = CAP: part number: CAP_0402-1000PF,CAP-42G0D001-D0,X7R,10%,50V
PC547 = CAP: part number: CAP_0402-33PF,CAP-42G0033P-C0,NP0,5%,50V
PC549 PC591 = CAP: part number: CAP_0402-6800PF,CAP-42FD0068-D0,X7R,10%,25V
PC552 PC554 PC556 PC557 PC1592 PC1594 PC1595 PC2596 = CAP: part number: CAP_0603-22UF,CAP-63B00022-E0,X6S,20%,4V
PC594-PC596 PC598-PC600 PC1596 PC1598-PC1600 = CAP: part number: CAP_0805-47UF,CAP-85B00047-E0,X6S,20%,4V
PL6 = INDUCTOR: part number: INDUCTOR_-2.2UH,IND-C104T2R2-M0,IC,20%,12A,
PL8 = INDUCTOR: part number: INDUCTOR_-4.7UH,IND-C063T4R7-M0,IC,20%,5.5A,
PL11 = INDUCTOR: part number: INDUCTOR_-0.36UH,IND-C104TR36-M0,IC,20%,30A,
PR332 = RES: part number: RES_0402-47K,RES-4200047K-B0,IC,1%,1/16W
PR333 = RES: part number: RES_0402-6.98K,RES-4206D98K-B0,IC,1%,1/16W
PR336 PR363 PR420 R1-R4 R7 R8 R77 R95-R106 R137 R141 R144 R145 R156 R159 R185 R186 R193 R194 R203 R204 R209 R210 R301 R348 = RES: part number: RES_0402-4.7K,RES-42004D7K-B0,IC,1%,1/16W
PR339 PR423 = RES: part number: RES_0402-39.2K,RES-42039D2K-B0,IC,1%,1/16W
PR340 PR341 PR348 PR369 PR370 PR375 PR424 PR426 = RES: part number: RES_0603-0,RES-63000000-C0,IC,5%,1A
PR342 = RES: part number: RES_0402-5.6K,RES-42005D6K-B0,IC,1%,1/16W
PR343 PR344 R277 R278 = RES: part number: RES_0402-2.2K,RES-42002D2K-B0,IC,1%,1/16W
PR345 PR347 PR428 PR429 = RES: part number: RES_0402-12.4K,RES-42012D4K-B0,IC,1%,1/16W
PR346 PR373 PR431 = RES: part number: RES_0402-120,RES-42000120-B0,IC,1%,1/16W
PR357 PR366 PR418 PR434 PR435 R5 R6 R21 R22 R25-R30 R85 R86 R89 R90 R118 R119 R130-R135 R150 R151 R157 R158 R211 R215 R221 R298 = RES: part number: RES_0402-0,RES-42000000-C0,IC,5%,1A
PR361 = RES: part number: RES_0402-6.34K,RES-4206D34K-B0,EMPTY,1%,1/16W
PR367 R9 R44 R45 R214 R216 R226-R228 R233-R237 R297 = RES: part number: RES_0402-0,RES-42000000-C0,EMPTY,5%,1A
PR368 = RES: part number: RES_0402-36.5K,RES-42036D5K-B0,IC,1%,1/16W
PR371 PR372 = RES: part number: RES_0402-4.99K,RES-4204D99K-F0,IC,0.1%,1/16W
PR374 PR430 R120 R129 R142 R143 R283 R285 R302 = RES: part number: RES_0402-10K,RES-4200010K-B0,IC,1%,1/16W
PR427 = RES: part number: RES_0402-6.19K,RES-4206D19K-B0,IC,1%,1/16W
PR432 = RES: part number: RES_0402-10.2K,RES-42010D2K-B0,IC,1%,1/16W
PR433 PR505 R59 R61 R65-R68 R71 R76 R80 R84 R107 R108 R112 R146-R148 R153 R160-R163 R191 R192 R199 R200 R282 R294 R318 = RES: part number: RES_0402-100,RES-42000100-B0,IC,1%,1/16W
PR504 = RES: part number: RES_0402-10,RES-42000010-B0,IC,1%,1/16W
PU17 = IR3899: part number: IR3899_-IR3899MTPRPBF,ICP-IR3899MT-00,IC,,
PU19 = IR3823_1: part number: IR3823_1_-IR3823MTRPBF,ICP-IR3823MT-00,IC,,,
PU23 = IR3895: part number: IR3895_-IR3895MTPRPBF,ICP-IR3895MT-00,IC,,
Q1-Q4 Q7 Q15 Q18-Q24 = 2N7002: part number: 2N7002_-2N7002,MOS-002N7002-00,IC,,,
Q5 Q6 Q25 = NPN: part number: NPN_-MMBT3904LT1G,BJT-MMBT3904-00,IC,,,
R10 = RES: part number: RES_0402-1.5K,RES-42001D5K-B0,IC,1%,1/16W
R11-R20 R23 R24 R31-R43 = RES: part number: RES_0402-3K,RES-4200003K-B0,IC,1%,1/16W
R46-R56 R87 R88 R252 R257-R264 R275 R296 R352 R353 = RES: part number: RES_0402-4.7K,RES-42004D7K-B0,EMPTY,1%,1/16W
R57 R60 R62 R70 R72 R74 R93 R94 R111 = RES: part number: RES_0402-1K,RES-4200001K-B0,EMPTY,1%,1/16W
R58 R63 R73 R75 R82 R114 R116 R284 R286 = RES: part number: RES_0402-100,RES-42000100-B0,EMPTY,1%,1/16W
R64 R69 R113 R115 R117 R121 R128 R351 = RES: part number: RES_0402-1K,RES-4200001K-B0,IC,1%,1/16W
R78 R81 = RES: part number: RES_0402-8.2K,RES-42008D2K-B0,IC,1%,1/16W
R79 R83 = RES: part number: RES_0402-8.2K,RES-42008D2K-B0,EMPTY,1%,1/16W
R91 R92 = RES: part number: RES_0402-2.2,RES-420002D2-B0,IC,1%,1/16W
R109 R281 R293 = RES: part number: RES_0402-10K,RES-4200010K-B0,EMPTY,1%,1/16W
R110 = RES: part number: RES_0402-300,RES-42000300-B0,IC,1%,1/16W
R122-R127 = RES: part number: RES_0402-27.4,RES-420027D4-B0,IC,1%,1/16W
R152 = RES: part number: RES_0402-100K,RES-4200100K-B0,IC,1%,1/16W
R154 = RES: part number: RES_0402-100K,RES-4200100K-B0,EMPTY,1%,1/16W
R183 R184 R279 R280 R299 R300 = RES: part number: RES_0402-22,RES-42000022-B0,IC,1%,1/16W
U1 = PEX8747CA80FBCG: part number: PEX8747CA80FBCG_-PEX8747-CA80FBC_G,ICC-PEX8747C-00,IC,,
U2 = PCA9548: part number: PCA9548_-PCA9548APW,ICC-PCA9548A-00,IC,,
U3 = TLA2024IRUGR: part number: TLA2024IRUGR_-TLA2024IRUGR,ICC-TLA2024I-00,IC,,
U4 = EMC1412: part number: EMC1412_-EMC1412-1-ACZL-TR,ICC-EMC14121-00,IC,,
U5 U25 U26 U29 U30 U33 U34 U37 U39 U41 U43 U45 = COUPON_7P: part number: COUPON_7P_-COUPON,,EMPTY,,
U6 = AT25256B: part number: AT25256B_-AT25256B-SSHL-T,ICM-AT25256B-00,IC,,
U7 = AT24C64D: part number: AT24C64D_-AT24C64D-SSHM-T,ICM-AT24C64D-00,IC,,
U8 U16 U17 = SN74LVC1G17: part number: SN74LVC1G17_-SN74LVC1G17DCKR,ICC-LVC1G17D-00,IC,,,
U9 = 9ZXL0651AKLFT: part number: 9ZXL0651AKLFT_-9ZXL0651AKLFT,ICC-9ZXL0651-00,IC,,
U10 = EMC1413AAIZLTR: part number: EMC1413AAIZLTR_-EMC1413-A-AIZL-TR,ICC-EMC1413A-00,IC,,
U11 = SN74AUP1T17DCKR: part number: SN74AUP1T17DCKR_-SN74AUP1T17DCKR,ICC-74AUP1T1-00,IC,,
U12 = PCA9617: part number: PCA9617_-PCA9617ADP,ICC-PCA9617A-00,IC,,
U19 U20 = SN74LVC1G07: part number: SN74LVC1G07_-SN74LVC1G07DCKR,ICC-LVC1G07D-00,IC,,,

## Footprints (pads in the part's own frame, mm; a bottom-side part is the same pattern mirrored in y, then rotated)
B2012
  rect 1.118x1.372 smd: 1(-0.95,0) 2(0.95,0)
BGA575_0-8_19-1X21
  round 0.406 smd: A1(-8.8,9.6) A2(-8,9.6) A3(-7.2,9.6) A4(-6.4,9.6) A5(-5.6,9.6) A6(-4.8,9.6) A7(-4,9.6) A8(-3.2,9.6) A9(-2.4,9.6) A10(-1.6,9.6) A11(-0.8,9.6) A12(0,9.6) A13(0.8,9.6) A14(1.6,9.6) A15(2.4,9.6) A16(3.2,9.6) A17(4,9.6) A18(4.8,9.6) A19(5.6,9.6) A20(6.4,9.6) A21(7.2,9.6) A22(8,9.6) A23(8.8,9.6) AA1(-8.8,-6.4) AA2(-8,-6.4) AA3(-7.2,-6.4) AA4(-6.4,-6.4) AA5(-5.6,-6.4) AA6(-4.8,-6.4) AA7(-4,-6.4) AA8(-3.2,-6.4) AA9(-2.4,-6.4) AA10(-1.6,-6.4) AA11(-0.8,-6.4) AA12(0,-6.4) AA13(0.8,-6.4) AA14(1.6,-6.4) AA15(2.4,-6.4) AA16(3.2,-6.4) AA17(4,-6.4) AA18(4.8,-6.4) AA19(5.6,-6.4) AA20(6.4,-6.4) AA21(7.2,-6.4) AA22(8,-6.4) AA23(8.8,-6.4) AB1(-8.8,-7.2) AB2(-8,-7.2) AB3(-7.2,-7.2) AB4(-6.4,-7.2) AB5(-5.6,-7.2) AB6(-4.8,-7.2) AB7(-4,-7.2) AB8(-3.2,-7.2) AB9(-2.4,-7.2) AB10(-1.6,-7.2) AB11(-0.8,-7.2) AB12(0,-7.2) AB13(0.8,-7.2) AB14(1.6,-7.2) AB15(2.4,-7.2) AB16(3.2,-7.2) AB17(4,-7.2) AB18(4.8,-7.2) AB19(5.6,-7.2) AB20(6.4,-7.2) AB21(7.2,-7.2) AB22(8,-7.2) AB23(8.8,-7.2) AC1(-8.8,-8) AC2(-8,-8) AC3(-7.2,-8) AC4(-6.4,-8) AC5(-5.6,-8) AC6(-4.8,-8) AC7(-4,-8) AC8(-3.2,-8) AC9(-2.4,-8) AC10(-1.6,-8) AC11(-0.8,-8) AC12(0,-8) AC13(0.8,-8) AC14(1.6,-8) AC15(2.4,-8) AC16(3.2,-8) AC17(4,-8) AC18(4.8,-8) AC19(5.6,-8) AC20(6.4,-8) AC21(7.2,-8) AC22(8,-8) AC23(8.8,-8) AD1(-8.8,-8.8) AD2(-8,-8.8) AD3(-7.2,-8.8) AD4(-6.4,-8.8) AD5(-5.6,-8.8) AD6(-4.8,-8.8) AD7(-4,-8.8) AD8(-3.2,-8.8) AD9(-2.4,-8.8) AD10(-1.6,-8.8) AD11(-0.8,-8.8) AD12(0,-8.8) AD13(0.8,-8.8) AD14(1.6,-8.8) AD15(2.4,-8.8) AD16(3.2,-8.8) AD17(4,-8.8) AD18(4.8,-8.8) AD19(5.6,-8.8) AD20(6.4,-8.8) AD21(7.2,-8.8) AD22(8,-8.8) AD23(8.8,-8.8) AE1(-8.8,-9.6) AE2(-8,-9.6) AE3(-7.2,-9.6) AE4(-6.4,-9.6) AE5(-5.6,-9.6) AE6(-4.8,-9.6) AE7(-4,-9.6) AE8(-3.2,-9.6) AE9(-2.4,-9.6) AE10(-1.6,-9.6) AE11(-0.8,-9.6) AE12(0,-9.6) AE13(0.8,-9.6) AE14(1.6,-9.6) AE15(2.4,-9.6) AE16(3.2,-9.6) AE17(4,-9.6) AE18(4.8,-9.6) AE19(5.6,-9.6) AE20(6.4,-9.6) AE21(7.2,-9.6) AE22(8,-9.6) AE23(8.8,-9.6) B1(-8.8,8.8) B2(-8,8.8) B3(-7.2,8.8) B4(-6.4,8.8) B5(-5.6,8.8) B6(-4.8,8.8) B7(-4,8.8) B8(-3.2,8.8) B9(-2.4,8.8) B10(-1.6,8.8) B11(-0.8,8.8) B12(0,8.8) B13(0.8,8.8) B14(1.6,8.8) B15(2.4,8.8) B16(3.2,8.8) B17(4,8.8) B18(4.8,8.8) B19(5.6,8.8) B20(6.4,8.8) B21(7.2,8.8) B22(8,8.8) B23(8.8,8.8) C1(-8.8,8) C2(-8,8) C3(-7.2,8) C4(-6.4,8) C5(-5.6,8) C6(-4.8,8) C7(-4,8) C8(-3.2,8) C9(-2.4,8) C10(-1.6,8) C11(-0.8,8) C12(0,8) C13(0.8,8) C14(1.6,8) C15(2.4,8) C16(3.2,8) C17(4,8) C18(4.8,8) C19(5.6,8) C20(6.4,8) C21(7.2,8) C22(8,8) C23(8.8,8) D1(-8.8,7.2) D2(-8,7.2) D3(-7.2,7.2) D4(-6.4,7.2) D5(-5.6,7.2) D6(-4.8,7.2) D7(-4,7.2) D8(-3.2,7.2) D9(-2.4,7.2) D10(-1.6,7.2) D11(-0.8,7.2) D12(0,7.2) D13(0.8,7.2) D14(1.6,7.2) D15(2.4,7.2) D16(3.2,7.2) D17(4,7.2) D18(4.8,7.2) D19(5.6,7.2) D20(6.4,7.2) D21(7.2,7.2) D22(8,7.2) D23(8.8,7.2) E1(-8.8,6.4) E2(-8,6.4) E3(-7.2,6.4) E4(-6.4,6.4) E5(-5.6,6.4) E6(-4.8,6.4) E7(-4,6.4) E8(-3.2,6.4) E9(-2.4,6.4) E10(-1.6,6.4) E11(-0.8,6.4) E12(0,6.4) E13(0.8,6.4) E14(1.6,6.4) E15(2.4,6.4) E16(3.2,6.4) E17(4,6.4) E18(4.8,6.4) E19(5.6,6.4) E20(6.4,6.4) E21(7.2,6.4) E22(8,6.4) E23(8.8,6.4) F1(-8.8,5.6) F2(-8,5.6) F3(-7.2,5.6) F4(-6.4,5.6) F5(-5.6,5.6) F6(-4.8,5.6) F7(-4,5.6) F8(-3.2,5.6) F9(-2.4,5.6) F10(-1.6,5.6) F11(-0.8,5.6) F12(0,5.6) F13(0.8,5.6) F14(1.6,5.6) F15(2.4,5.6) F16(3.2,5.6) F17(4,5.6) F18(4.8,5.6) F19(5.6,5.6) F20(6.4,5.6) F21(7.2,5.6) F22(8,5.6) F23(8.8,5.6) G1(-8.8,4.8) G2(-8,4.8) G3(-7.2,4.8) G4(-6.4,4.8) G5(-5.6,4.8) G6(-4.8,4.8) G7(-4,4.8) G8(-3.2,4.8) G9(-2.4,4.8) G10(-1.6,4.8) G11(-0.8,4.8) G12(0,4.8) G13(0.8,4.8) G14(1.6,4.8) G15(2.4,4.8) G16(3.2,4.8) G17(4,4.8) G18(4.8,4.8) G19(5.6,4.8) G20(6.4,4.8) G21(7.2,4.8) G22(8,4.8) G23(8.8,4.8) H1(-8.8,4) H2(-8,4) H3(-7.2,4) H4(-6.4,4) H5(-5.6,4) H6(-4.8,4) H7(-4,4) H8(-3.2,4) H9(-2.4,4) H10(-1.6,4) H11(-0.8,4) H12(0,4) H13(0.8,4) H14(1.6,4) H15(2.4,4) H16(3.2,4) H17(4,4) H18(4.8,4) H19(5.6,4) H20(6.4,4) H21(7.2,4) H22(8,4) H23(8.8,4) J1(-8.8,3.2) J2(-8,3.2) J3(-7.2,3.2) J4(-6.4,3.2) J5(-5.6,3.2) J6(-4.8,3.2) J7(-4,3.2) J8(-3.2,3.2) J9(-2.4,3.2) J10(-1.6,3.2) J11(-0.8,3.2) J12(0,3.2) J13(0.8,3.2) J14(1.6,3.2) J15(2.4,3.2) J16(3.2,3.2) J17(4,3.2) J18(4.8,3.2) J19(5.6,3.2) J20(6.4,3.2) J21(7.2,3.2) J22(8,3.2) J23(8.8,3.2) K1(-8.8,2.4) K2(-8,2.4) K3(-7.2,2.4) K4(-6.4,2.4) K5(-5.6,2.4) K6(-4.8,2.4) K7(-4,2.4) K8(-3.2,2.4) K9(-2.4,2.4) K10(-1.6,2.4) K11(-0.8,2.4) K12(0,2.4) K13(0.8,2.4) K14(1.6,2.4) K15(2.4,2.4) K16(3.2,2.4) K17(4,2.4) K18(4.8,2.4) K19(5.6,2.4) K20(6.4,2.4) K21(7.2,2.4) K22(8,2.4) K23(8.8,2.4) L1(-8.8,1.6) L2(-8,1.6) L3(-7.2,1.6) L4(-6.4,1.6) L5(-5.6,1.6) L6(-4.8,1.6) L7(-4,1.6) L8(-3.2,1.6) L9(-2.4,1.6) L10(-1.6,1.6) L11(-0.8,1.6) L12(0,1.6) L13(0.8,1.6) L14(1.6,1.6) L15(2.4,1.6) L16(3.2,1.6) L17(4,1.6) L18(4.8,1.6) L19(5.6,1.6) L20(6.4,1.6) L21(7.2,1.6) L22(8,1.6) L23(8.8,1.6) M1(-8.8,0.8) M2(-8,0.8) M3(-7.2,0.8) M4(-6.4,0.8) M5(-5.6,0.8) M6(-4.8,0.8) M7(-4,0.8) M8(-3.2,0.8) M9(-2.4,0.8) M10(-1.6,0.8) M11(-0.8,0.8) M12(0,0.8) M13(0.8,0.8) M14(1.6,0.8) M15(2.4,0.8) M16(3.2,0.8) M17(4,0.8) M18(4.8,0.8) M19(5.6,0.8) M20(6.4,0.8) M21(7.2,0.8) M22(8,0.8) M23(8.8,0.8) N1(-8.8,0) N2(-8,0) N3(-7.2,0) N4(-6.4,0) N5(-5.6,0) N6(-4.8,0) N7(-4,0) N8(-3.2,0) N9(-2.4,0) N10(-1.6,0) N11(-0.8,0) N12(0,0) N13(0.8,0) N14(1.6,0) N15(2.4,0) N16(3.2,0) N17(4,0) N18(4.8,0) N19(5.6,0) N20(6.4,0) N21(7.2,0) N22(8,0) N23(8.8,0) P1(-8.8,-0.8) P2(-8,-0.8) P3(-7.2,-0.8) P4(-6.4,-0.8) P5(-5.6,-0.8) P6(-4.8,-0.8) P7(-4,-0.8) P8(-3.2,-0.8) P9(-2.4,-0.8) P10(-1.6,-0.8) P11(-0.8,-0.8) P12(0,-0.8) P13(0.8,-0.8) P14(1.6,-0.8) P15(2.4,-0.8) P16(3.2,-0.8) P17(4,-0.8) P18(4.8,-0.8) P19(5.6,-0.8) P20(6.4,-0.8) P21(7.2,-0.8) P22(8,-0.8) P23(8.8,-0.8) R1(-8.8,-1.6) R2(-8,-1.6) R3(-7.2,-1.6) R4(-6.4,-1.6) R5(-5.6,-1.6) R6(-4.8,-1.6) R7(-4,-1.6) R8(-3.2,-1.6) R9(-2.4,-1.6) R10(-1.6,-1.6) R11(-0.8,-1.6) R12(0,-1.6) R13(0.8,-1.6) R14(1.6,-1.6) R15(2.4,-1.6) R16(3.2,-1.6) R17(4,-1.6) R18(4.8,-1.6) R19(5.6,-1.6) R20(6.4,-1.6) R21(7.2,-1.6) R22(8,-1.6) R23(8.8,-1.6) T1(-8.8,-2.4) T2(-8,-2.4) T3(-7.2,-2.4) T4(-6.4,-2.4) T5(-5.6,-2.4) T6(-4.8,-2.4) T7(-4,-2.4) T8(-3.2,-2.4) T9(-2.4,-2.4) T10(-1.6,-2.4) T11(-0.8,-2.4) T12(0,-2.4) T13(0.8,-2.4) T14(1.6,-2.4) T15(2.4,-2.4) T16(3.2,-2.4) T17(4,-2.4) T18(4.8,-2.4) T19(5.6,-2.4) T20(6.4,-2.4) T21(7.2,-2.4) T22(8,-2.4) T23(8.8,-2.4) U1(-8.8,-3.2) U2(-8,-3.2) U3(-7.2,-3.2) U4(-6.4,-3.2) U5(-5.6,-3.2) U6(-4.8,-3.2) U7(-4,-3.2) U8(-3.2,-3.2) U9(-2.4,-3.2) U10(-1.6,-3.2) U11(-0.8,-3.2) U12(0,-3.2) U13(0.8,-3.2) U14(1.6,-3.2) U15(2.4,-3.2) U16(3.2,-3.2) U17(4,-3.2) U18(4.8,-3.2) U19(5.6,-3.2) U20(6.4,-3.2) U21(7.2,-3.2) U22(8,-3.2) U23(8.8,-3.2) V1(-8.8,-4) V2(-8,-4) V3(-7.2,-4) V4(-6.4,-4) V5(-5.6,-4) V6(-4.8,-4) V7(-4,-4) V8(-3.2,-4) V9(-2.4,-4) V10(-1.6,-4) V11(-0.8,-4) V12(0,-4) V13(0.8,-4) V14(1.6,-4) V15(2.4,-4) V16(3.2,-4) V17(4,-4) V18(4.8,-4) V19(5.6,-4) V20(6.4,-4) V21(7.2,-4) V22(8,-4) V23(8.8,-4) W1(-8.8,-4.8) W2(-8,-4.8) W3(-7.2,-4.8) W4(-6.4,-4.8) W5(-5.6,-4.8) W6(-4.8,-4.8) W7(-4,-4.8) W8(-3.2,-4.8) W9(-2.4,-4.8) W10(-1.6,-4.8) W11(-0.8,-4.8) W12(0,-4.8) W13(0.8,-4.8) W14(1.6,-4.8) W15(2.4,-4.8) W16(3.2,-4.8) W17(4,-4.8) W18(4.8,-4.8) W19(5.6,-4.8) W20(6.4,-4.8) W21(7.2,-4.8) W22(8,-4.8) W23(8.8,-4.8) Y1(-8.8,-5.6) Y2(-8,-5.6) Y3(-7.2,-5.6) Y4(-6.4,-5.6) Y5(-5.6,-5.6) Y6(-4.8,-5.6) Y7(-4,-5.6) Y8(-3.2,-5.6) Y9(-2.4,-5.6) Y10(-1.6,-5.6) Y11(-0.8,-5.6) Y12(0,-5.6) Y13(0.8,-5.6) Y14(1.6,-5.6) Y15(2.4,-5.6) Y16(3.2,-5.6) Y17(4,-5.6) Y18(4.8,-5.6) Y19(5.6,-5.6) Y20(6.4,-5.6) Y21(7.2,-5.6) Y22(8,-5.6) Y23(8.8,-5.6)
C0201
  rect 0.279x0.33 smd: 1(-0.229,0) 2(0.229,0)
C0201#2
  rect 0.305x0.381 smd: 1(-0.267,0) 2(0.267,0)
C0402
  rect 0.457x0.508 smd: 1(-0.4,0) 2(0.4,0)
C0603
  rect 0.813x0.711 smd: 1(-0.737,0) 2(0.737,0)
C0805
  rect 1.118x1.372 smd: 1(-0.95,0) 2(0.95,0)
C1206
  rect 1.168x1.575 smd: 1(-1.473,0) 2(1.473,0)
DELTAL_COUPON_7P
  round 0.66 smd: 1(-0.504,1.301) 2(0.497,1.301)
  round 1.143 hole 1.041: 3(-1.274,-2.498) 4(1.266,-2.498) 5(-1.274,3.852) 6(1.266,3.852)
  custom 0.743x0.743 smd: 7(-0.009,-0.37)
  round 0.508 hole 0.406: 8(-1.27,0.457) 9(-1.27,-0.762) 10(-0.025,-0.762) 11(1.27,-0.762) 12(1.27,0.457)
GF_PCIE_X16
  rect 0.762x3.2 smd: A1(-11.5,-3.42) B81(70.5,-3.42)
  rect 0.762x4.216 smd: A2(-10.5,-3.92) A3(-9.5,-3.92) A4(-8.5,-3.92) A5(-7.5,-3.92) A6(-6.5,-3.92) A7(-5.5,-3.92) A8(-4.5,-3.92) A9(-3.5,-3.92) A10(-2.5,-3.92) A11(-1.5,-3.92) A12(1.5,-3.92) A13(2.5,-3.92) A14(3.5,-3.92) A15(4.5,-3.92) A16(5.5,-3.92) A17(6.5,-3.92) A18(7.5,-3.92) A19(8.5,-3.92) A20(9.5,-3.92) A21(10.5,-3.92) A22(11.5,-3.92) A23(12.5,-3.92) A24(13.5,-3.92) A25(14.5,-3.92) A26(15.5,-3.92) A27(16.5,-3.92) A28(17.5,-3.92) A29(18.5,-3.92) A30(19.5,-3.92) A31(20.5,-3.92) A32(21.5,-3.92) A33(22.5,-3.92) A34(23.5,-3.92) A35(24.5,-3.92) A36(25.5,-3.92) A37(26.5,-3.92) A38(27.5,-3.92) A39(28.5,-3.92) A40(29.5,-3.92) A41(30.5,-3.92) A42(31.5,-3.92) A43(32.5,-3.92) A44(33.5,-3.92) A45(34.5,-3.92) A46(35.5,-3.92) A47(36.5,-3.92) A48(37.5,-3.92) A49(38.5,-3.92) A50(39.5,-3.92) A51(40.5,-3.92) A52(41.5,-3.92) A53(42.5,-3.92) A54(43.5,-3.92) A55(44.5,-3.92) A56(45.5,-3.92) A57(46.5,-3.92) A58(47.5,-3.92) A59(48.5,-3.92) A60(49.5,-3.92) A61(50.5,-3.92) A62(51.5,-3.92) A63(52.5,-3.92) A64(53.5,-3.92) A65(54.5,-3.92) A66(55.5,-3.92) A67(56.5,-3.92) A68(57.5,-3.92) A69(58.5,-3.92) A70(59.5,-3.92) A71(60.5,-3.92) A72(61.5,-3.92) A73(62.5,-3.92) A74(63.5,-3.92) A75(64.5,-3.92) A76(65.5,-3.92) A77(66.5,-3.92) A78(67.5,-3.92) A79(68.5,-3.92) A80(69.5,-3.92) A81(70.5,-3.92) A82(71.5,-3.92) B1(-11.5,-3.92) B2(-10.5,-3.92) B3(-9.5,-3.92) B4(-8.5,-3.92) B5(-7.5,-3.92) B6(-6.5,-3.92) B7(-5.5,-3.92) B8(-4.5,-3.92) B9(-3.5,-3.92) B10(-2.5,-3.92) B11(-1.5,-3.92) B12(1.5,-3.92) B13(2.5,-3.92) B14(3.5,-3.92) B15(4.5,-3.92) B16(5.5,-3.92) B17(6.5,-3.92) B18(7.5,-3.92) B19(8.5,-3.92) B20(9.5,-3.92) B21(10.5,-3.92) B22(11.5,-3.92) B23(12.5,-3.92) B24(13.5,-3.92) B25(14.5,-3.92) B26(15.5,-3.92) B27(16.5,-3.92) B28(17.5,-3.92) B29(18.5,-3.92) B30(19.5,-3.92) B31(20.5,-3.92) B32(21.5,-3.92) B33(22.5,-3.92) B34(23.5,-3.92) B35(24.5,-3.92) B36(25.5,-3.92) B37(26.5,-3.92) B38(27.5,-3.92) B39(28.5,-3.92) B40(29.5,-3.92) B41(30.5,-3.92) B42(31.5,-3.92) B43(32.5,-3.92) B44(33.5,-3.92) B45(34.5,-3.92) B46(35.5,-3.92) B47(36.5,-3.92) B48(37.5,-3.92) B49(38.5,-3.92) B50(39.5,-3.92) B51(40.5,-3.92) B52(41.5,-3.92) B53(42.5,-3.92) B54(43.5,-3.92) B55(44.5,-3.92) B56(45.5,-3.92) B57(46.5,-3.92) B58(47.5,-3.92) B59(48.5,-3.92) B60(49.5,-3.92) B61(50.5,-3.92) B62(51.5,-3.92) B63(52.5,-3.92) B64(53.5,-3.92) B65(54.5,-3.92) B66(55.5,-3.92) B67(56.5,-3.92) B68(57.5,-3.92) B69(58.5,-3.92) B70(59.5,-3.92) B71(60.5,-3.92) B72(61.5,-3.92) B73(62.5,-3.92) B74(63.5,-3.92) B75(64.5,-3.92) B76(65.5,-3.92) B77(66.5,-3.92) B78(67.5,-3.92) B79(68.5,-3.92) B80(69.5,-3.92) B82(71.5,-3.92)
GND_C10D4_6-5B10_OB5
  round 4.013 hole 4.013 unplated: (0,0)
  round 0.762 hole 0.559: 2(-3.5,0) 3(-2.475,2.475) 4(0,3.5) 5(2.475,2.475) 6(3.5,0)
HEADER1X4S2NH_P2H2_RA
  round 1.194 hole 1.194 unplated: (-2,-0.013) (2,-0.013)
  rect 1.041x2.032 smd: 1(-3,-3.188) 2(-1,-3.188) 3(1,-3.188) 4(3,-3.188)
HOLE_C10D5-6B10_NPB_H11_STANDOFF
  round 10.008 hole 5.613: 1(0,0)
HOLE_D3N_PKO10
  round 3.023 hole 3.023 unplated: (0,0)
IND_PCMB104T
  rect 4.115x4.115 smd: 1(-4.75,0) 2(4.75,0)
IND_PCMB104TXA
  rect 4.115x4.115 smd: 1(-4.75,0) 2(4.75,0)
IND_PCMC063T
  rect 2.362x3.505 smd: 1(-3.025,0) 2(3.025,0)
LED0603
  rect 0.813x0.813 smd: A(-0.75,0) C(0.75,0)
MSOP8_P0-65H1-1
  rect 1.6x0.305 smd: 1(-2,0.975) 2(-2,0.325) 3(-2,-0.325) 4(-2,-0.975) 5(2,-0.975) 6(2,-0.325) 7(2,0.325) 8(2,0.975)
MSOP10_P0-5W4-4_3X3
  rect 1.422x0.279 smd: 1(-2.2,1) 2(-2.2,0.5) 3(-2.2,0) 4(-2.2,-0.5) 5(-2.2,-1) 6(2.2,-1) 7(2.2,-0.5) 8(2.2,0) 9(2.2,0.5) 10(2.2,1)
